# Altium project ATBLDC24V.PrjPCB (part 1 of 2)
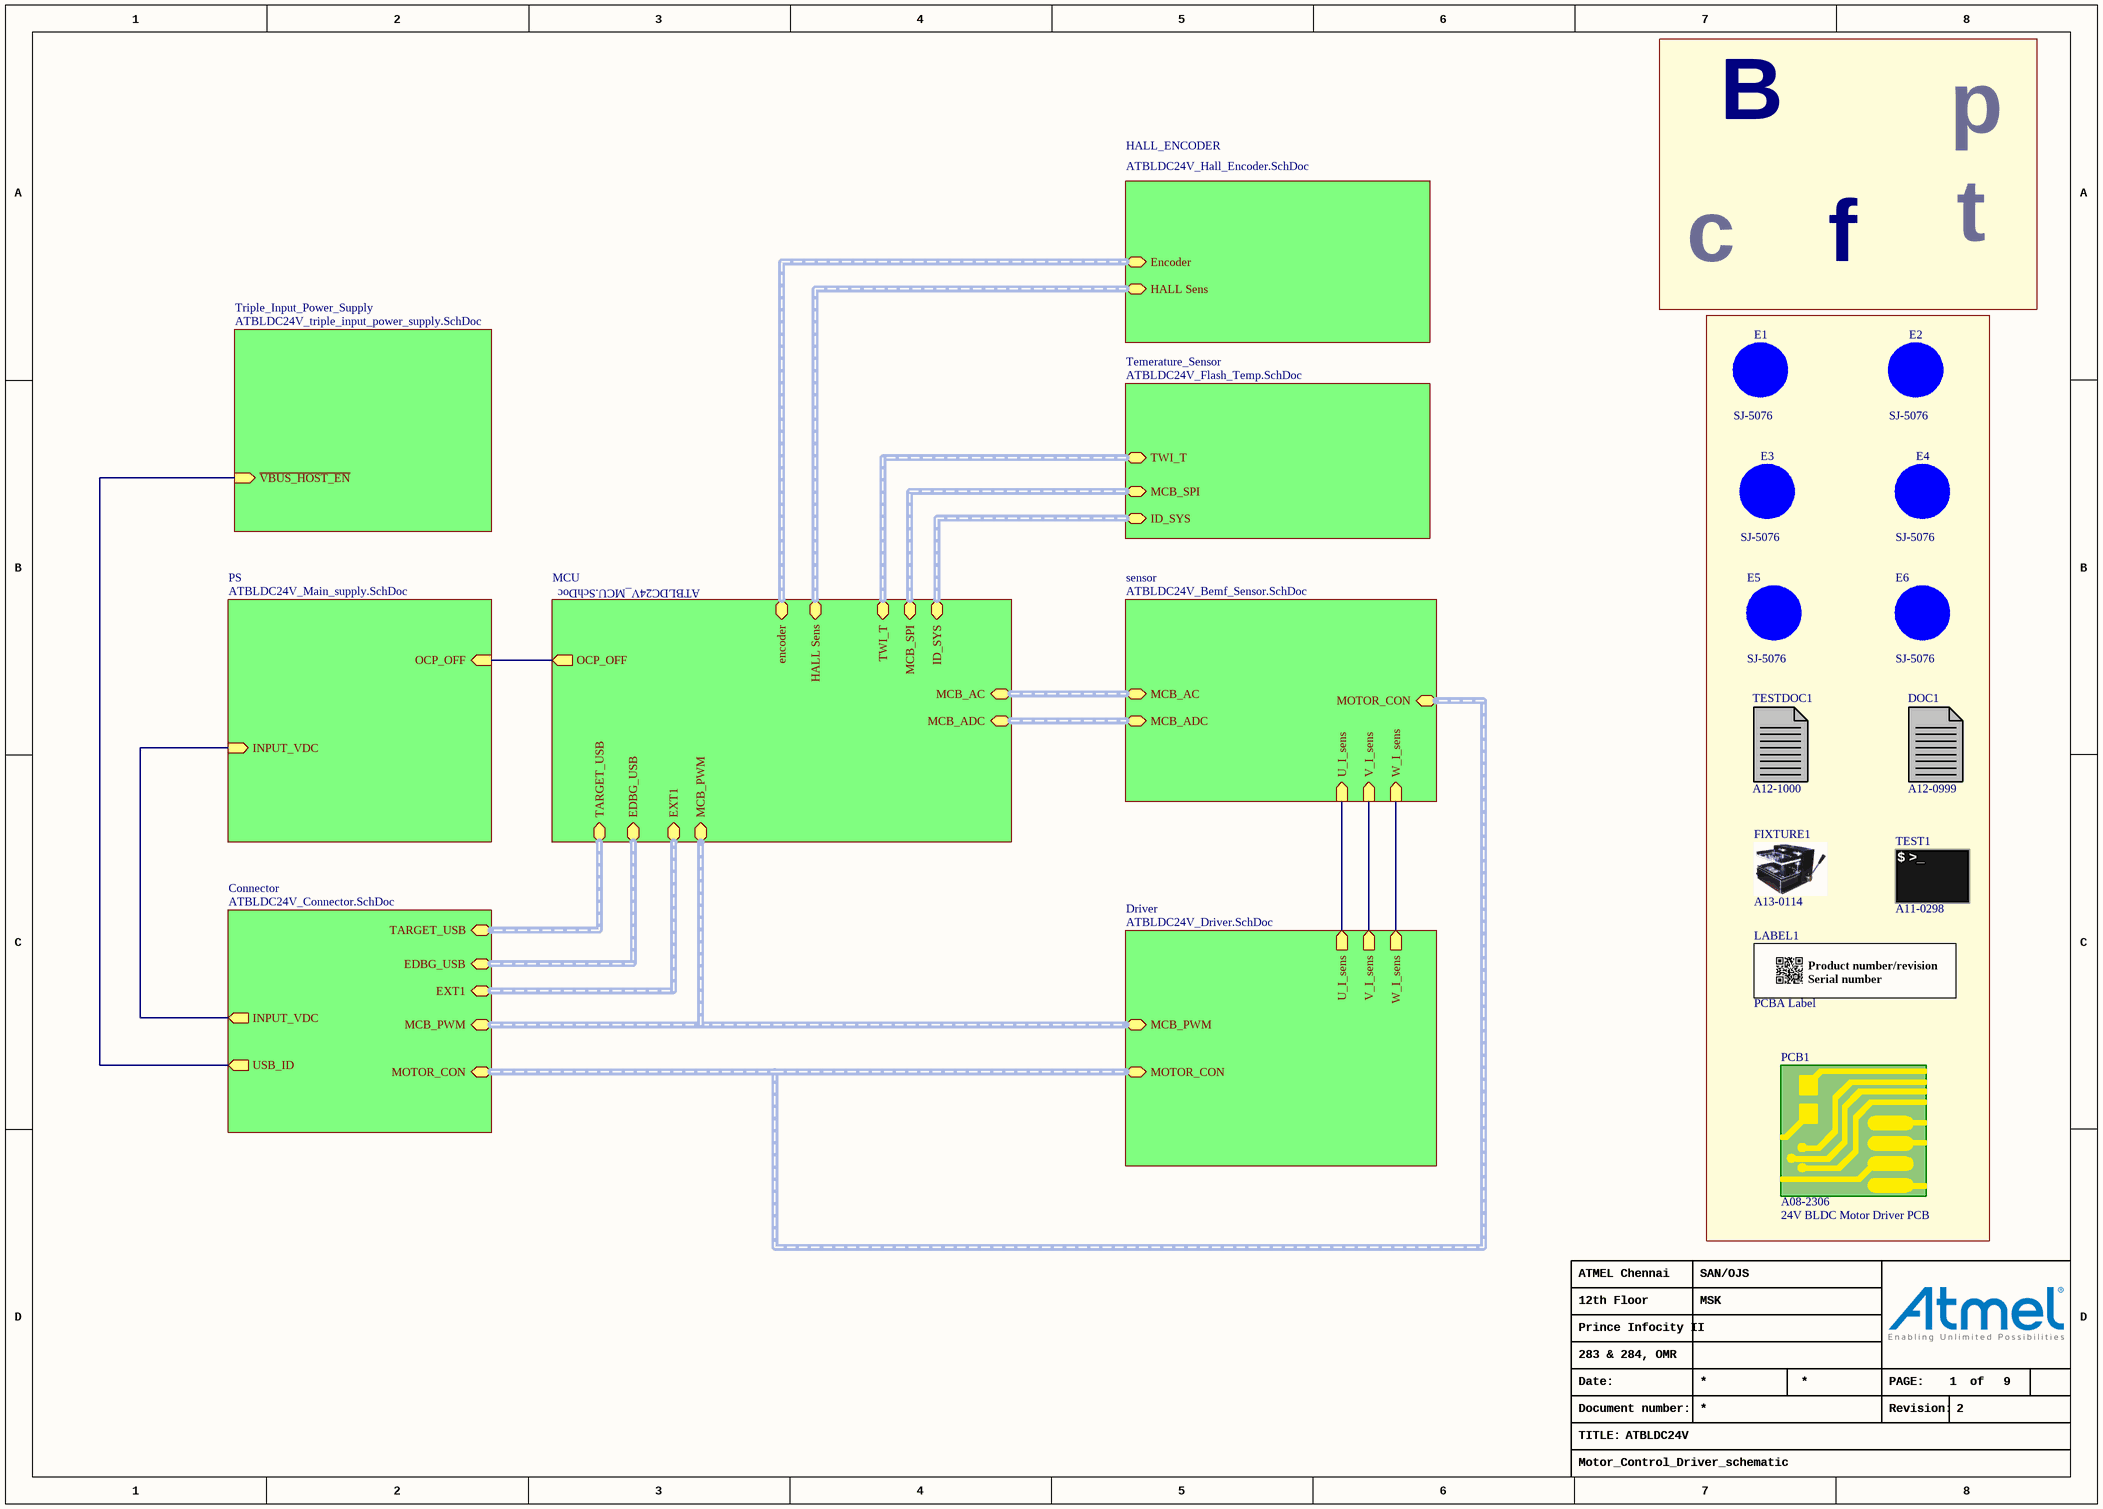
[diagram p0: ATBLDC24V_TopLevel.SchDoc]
9 sheets, 345 parts. Net scope: hierarchical (ports join the sheet entries above them; power ports are global).
Board file: ATBLDC24V.PcbDoc
Sheets:
  ATBLDC24V_TopLevel.SchDoc
    PS = ATBLDC24V_Main_supply.SchDoc
    Driver = ATBLDC24V_Driver.SchDoc
    Connector = ATBLDC24V_Connector.SchDoc
    sensor = ATBLDC24V_Bemf_Sensor.SchDoc
    MCU = ATBLDC24V_MCU.SchDoc
    Temerature_Sensor = ATBLDC24V_Flash_Temp.SchDoc
    Triple_Input_Power_Supply = ATBLDC24V_triple_input_power_supply.SchDoc
    HALL_ENCODER = ATBLDC24V_Hall_Encoder.SchDoc

## Sheet ATBLDC24V_TopLevel.SchDoc: ATBLDC24V
size A3; Organization: ATMEL Chennai; Address1: 12th Floor; Address2: Prince Infocity II; Address3: 283 & 284, OMR; Address4: Chennai; Revision: 2; SheetNumber: 1; SheetTotal: 9; CheckedBy: MSK; DrawnBy: SAN/OJS; Engineer: SAN/OJS; PageSetup: Record=PageOptions¦CenterHorizontal=True¦CenterVertical=True¦PrintScale=0.70¦XCorrection=1.00¦YCorrection=1.00¦PrintKind=0¦BorderSize=5000000¦LeftOffset=0¦BottomOffset=0¦Orientation=2¦PaperLength=1000¦PaperWidth=1000¦Scale=100¦PaperSource=7¦PrintQuality=-4¦MediaType=1¦DitherType=10¦PaperKind=Letter¦PrintScaleMode=1

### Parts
DOC1  AN: A12-0999  (hidden comment: DOCUMENTATION)  (mechanical)
E1  value SJ-5076  [AP8-00192]
E2  value SJ-5076  [AP8-00192]
E3  value SJ-5076  [AP8-00192]
E4  value SJ-5076  [AP8-00192]
E5  value SJ-5076  [AP8-00192]  (hidden comment: RUBBER FEET)
E6  value SJ-5076  [AP8-00192]  (hidden comment: RUBBER FEET)
FIXTURE1  AN: A13-0114  (hidden comment: JIG)  (mechanical)
LABEL1  value PCBA Label  [AP8-00317]  (hidden comment: PCBA_LABEL)
PCB1  value 24V BLDC Motor Driver PCB  AN: A08-2306  (hidden comment: PCB)  (mechanical)
TEST1  AN: A11-0298  (hidden comment: TEST)  (mechanical)
TESTDOC1  AN: A12-1000  (hidden comment: TESTDOC)  (mechanical)

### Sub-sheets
Connector = ATBLDC24V_Connector.SchDoc: EXT1 (harness EXT1), MCB_PWM (harness MCB_PWM), MOTOR_CON (harness MOTOR_CON), INPUT_VDC (out), EDBG_USB (harness EDBG_USB), TARGET_USB (harness TARGET_USB), USB_ID (out)
Driver = ATBLDC24V_Driver.SchDoc: MOTOR_CON (harness MOTOR_CON), MCB_PWM (harness MCB_PWM), W_I_sens (out), V_I_sens (out), U_I_sens (out)
HALL_ENCODER = ATBLDC24V_Hall_Encoder.SchDoc: HALL Sens (harness Hall Sensor), Encoder (harness Encoder)
MCU = ATBLDC24V_MCU.SchDoc: MCB_ADC (harness MCB_ADC), MCB_AC (harness MCB_AC), MCB_PWM (harness MCB_PWM), MCB_SPI (harness MCB_SPI), EXT1 (harness EXT1), ID_SYS (harness ID_SYS), TWI_T (harness TWI_T), EDBG_USB (harness EDBG_USB), TARGET_USB (harness TARGET_USB), HALL Sens (harness Hall Sensor), encoder (harness Encoder), OCP_OFF (out)
PS = ATBLDC24V_Main_supply.SchDoc: INPUT_VDC (in), OCP_OFF (in)
sensor = ATBLDC24V_Bemf_Sensor.SchDoc: MCB_AC (harness MCB_AC), MCB_ADC (harness MCB_ADC), W_I_sens (in), V_I_sens (in), U_I_sens (in), MOTOR_CON (harness MOTOR_CON)
Temerature_Sensor = ATBLDC24V_Flash_Temp.SchDoc: TWI_T (harness TWI_T), ID_SYS (harness ID_SYS), MCB_SPI (harness MCB_SPI)
Triple_Input_Power_Supply = ATBLDC24V_triple_input_power_supply.SchDoc: ~{VBUS_HOST_EN} (in)

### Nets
GPIO8: sheet PS/OCP_OFF, sheet MCU/OCP_OFF
TARGET_USB_ID: sheet Connector/USB_ID, sheet Triple_Input_Power_Supply/~{VBUS_HOST_EN}
USHUNT_ADC: sheet Driver/U_I_sens, sheet sensor/U_I_sens
VSHUNT_ADC: sheet Driver/V_I_sens, sheet sensor/V_I_sens
WSHUNT_ADC: sheet Driver/W_I_sens, sheet sensor/W_I_sens
NetCONN1_1: sheet PS/INPUT_VDC, sheet Connector/INPUT_VDC

Not connected (* = marked no-connect by the designer): E1 1(FIDUCIAL); E2 1(FIDUCIAL); E3 1(FIDUCIAL); E4 1(FIDUCIAL); E5 1(FIDUCIAL); E6 1(FIDUCIAL)

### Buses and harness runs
harness sheet Connector/EDBG_USB = sheet MCU/EDBG_USB
harness sheet Connector/EXT1 = sheet MCU/EXT1
harness sheet Connector/MCB_PWM = sheet Driver/MCB_PWM = sheet MCU/MCB_PWM
harness sheet Connector/MOTOR_CON = sheet Driver/MOTOR_CON = sheet sensor/MOTOR_CON
harness sheet Connector/TARGET_USB = sheet MCU/TARGET_USB
harness sheet HALL_ENCODER/Encoder = sheet MCU/encoder
harness sheet HALL_ENCODER/HALL Sens = sheet MCU/HALL Sens
harness sheet MCU/ID_SYS = sheet Temerature_Sensor/ID_SYS
harness sheet MCU/MCB_AC = sheet sensor/MCB_AC
harness sheet MCU/MCB_ADC = sheet sensor/MCB_ADC
harness sheet MCU/MCB_SPI = sheet Temerature_Sensor/MCB_SPI
harness sheet MCU/TWI_T = sheet Temerature_Sensor/TWI_T

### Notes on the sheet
- B
- p
- c
- f
- t
- Date:
- PAGE:
- of
- TITLE:
- Document number:
- Revision:

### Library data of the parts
DOC1 = A12-0999: 24V BLDC Motor Driver PCBA; PartGroup: Documentation,PCBA Documents,Atmel
E1-E6 = A08-0053: 2.8mm adhesive feet,diam 8.0mm; PartGroup: Mechanical devices,Mounting accessories; Manufacturer: 3M
FIXTURE1 = A13-0114: Test Fixture for BLDC Motor driver; PartGroup: Test Equipment,Test Fixtures
LABEL1 = A09-0611: PCBA identification label PP Top White Gloss; PartGroup: Mechanical devices,Packaging materials,Printed Labels; Manufacturer: ACT Logimark AS; MPN: 505462
PCB1 = A08-2306: 24V BLDC Motor Driver PCB; PartGroup: Mechanical devices,Printed circuit boards; TemperatureRange: -40 deg C to +150 deg C
TEST1 = A11-0298: Fixture test SW for BLDC Motor driver; PartGroup: Software,Test software,Starter Kit
TESTDOC1 = A12-1000: BLDC Motor Driver production Test Instructions; PartGroup: Documentation,Procedures,Test Instructions

## Sheet ATBLDC24V_Main_supply.SchDoc: ATBLDC24V_schematic
size A3; Organization: ATMEL Chennai; Address1: 12th Floor; Address2: Prince Infocity II; Address3: 283 & 284, OMR; Address4: Chennai; Revision: 2; SheetNumber: 2; SheetTotal: 9; CheckedBy: MSK; DrawnBy: SAN/OJS; Engineer: SAN/OJS; PageSetup: Record=PageOptions¦CenterHorizontal=True¦CenterVertical=True¦PrintScale=1.01¦XCorrection=1.00¦YCorrection=1.00¦PrintKind=1¦BorderSize=5000000¦LeftOffset=0¦BottomOffset=0¦Orientation=2¦PaperLength=1000¦PaperWidth=1000¦Scale=100¦PaperSource=7¦PrintQuality=-4¦MediaType=1¦DitherType=10¦PaperKind=A3 (297 x 420 mm)¦PrintScaleMode=1
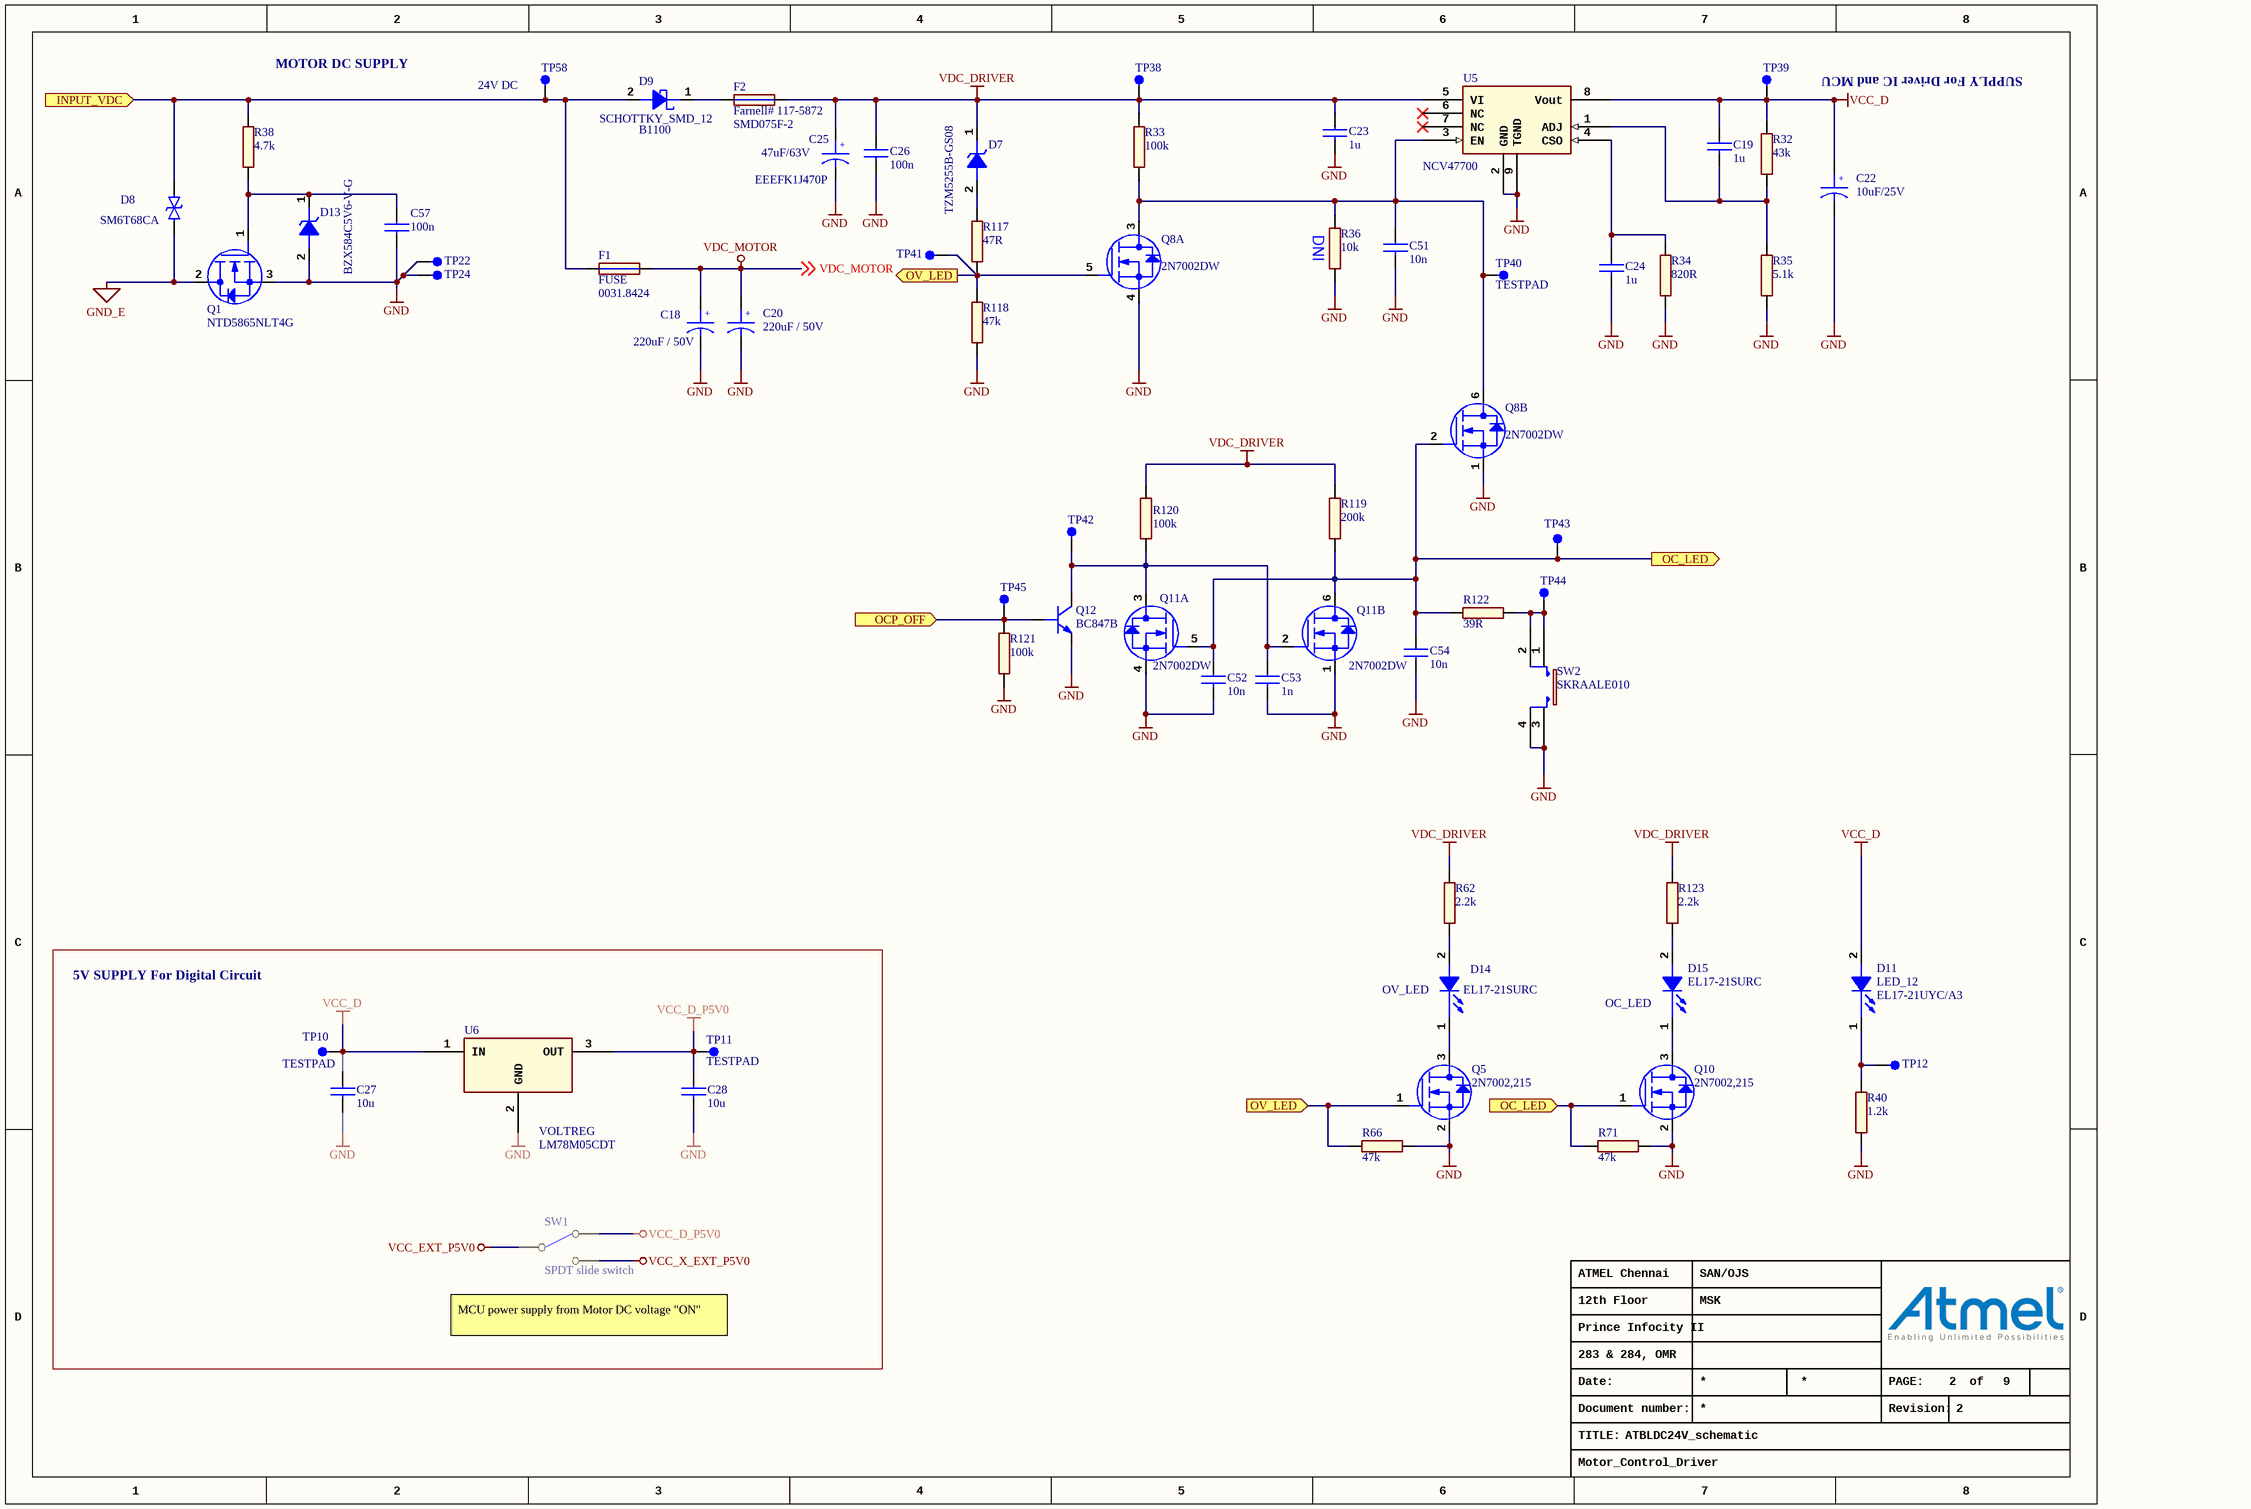
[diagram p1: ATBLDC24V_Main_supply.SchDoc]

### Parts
C18  value 220uF / 50V  [AP1-00025]  (hidden comment: CAP-POL)
C19  value 1u  [AP1-00003]  (hidden comment: CAP-NONPOL)
C20  value 220uF / 50V  [AP1-00025]  (hidden comment: CAP-POL)
C22  value 10uF/25V  [AP1-00013]  (hidden comment: CAP-POL)
C23  value 1u  [AP1-00003]  (hidden comment: CAP-NONPOL)
C24  value 1u  [AP1-00003]  (hidden comment: CAP-NONPOL)
C25  47uF/63V  value EEEFK1J470P  [AP1-00012]
C26  value 100n  [AP1-00003]  (hidden comment: CAP-NONPOL)
C27  value 10u  [AP1-00003]  (hidden comment: CAP-NONPOL)
C28  value 10u  [AP1-00003]  (hidden comment: CAP-NONPOL)
C51  value 10n  [AP1-00002]  (hidden comment: CAP-NONPOL)
C52  value 10n  [AP1-00001]  (hidden comment: CAP-NONPOL)
C53  value 1n  [AP1-00001]  (hidden comment: CAP-NONPOL)
C54  value 10n  [AP1-00001]  (hidden comment: CAP-NONPOL)
C57  value 100n  [AP1-00003]  (hidden comment: CAP-NONPOL)
D7  value TZM5255B-GS08  (hidden comment: ZENER_SMD_12)
D8  value SM6T68CA  [AP4-00002]  (hidden comment: TransGuard)
D9  SCHOTTKY_SMD_12  value B1100  [AP4-00038]
D11  LED_12  value EL17-21UYC/A3  [AP4-00013]
D13  value BZX584C5V6-V-G  [AP4-00036]  (hidden comment: ZENER_SMD_12)
D14  value EL17-21SURC  [AP4-00013]  (hidden comment: LED_12)
D15  value EL17-21SURC  [AP4-00013]  (hidden comment: LED_12)
F1  FUSE  value 0031.8424  [AP8-00249]
F2  Farnell# 117-5872  value SMD075F-2  [AP2-00018]
Q1  value NTD5865NLT4G  (hidden comment: MOSFET_N_DPAK)
Q5  value 2N7002,215  [AP5-00002]  (hidden comment: MOSFET_N_GSD)
Q8  value 2N7002DW  [AP5-00001]  (hidden comment: Same as 2N7002 but with two MOSFETs in one package)  (parts A,B of 2)
Q10  value 2N7002,215  [AP5-00002]  (hidden comment: MOSFET_N_GSD)
Q11  value 2N7002DW  [AP5-00001]  (hidden comment: Same as 2N7002 but with two MOSFETs in one package)  (parts A,B of 2)
Q12  value BC847B  [AP5-00002]  (hidden comment: NPN BEC)
R32  value 43k  [AP2-00001]  (hidden comment: R2)
R33  value 100k  [AP2-00001]  (hidden comment: R2)
R34  value 820R  [AP2-00001]  (hidden comment: R2)
R35  value 5.1k  [AP2-00001]  (hidden comment: R2)
R36  value 10k  [AP2-00000]  (hidden comment: R2)
R38  value 4.7k  [AP2-00001]  (hidden comment: R2)
R40  value 1.2k  [AP2-00001]  (hidden comment: R2)
R62  value 2.2k  [AP2-00001]  (hidden comment: R2)
R66  value 47k  [AP2-00000]  (hidden comment: R2)
R71  value 47k  [AP2-00000]  (hidden comment: R2)
R117  value 47R  [AP2-00001]  (hidden comment: R2)
R118  value 47k  [AP2-00000]  (hidden comment: R2)
R119  value 200k  [AP2-00001]  (hidden comment: R2)
R120  value 100k  [AP2-00001]  (hidden comment: R2)
R121  value 100k  [AP2-00000]  (hidden comment: R2)
R122  value 39R  [AP2-00001]  (hidden comment: R2)
R123  value 2.2k  [AP2-00001]  (hidden comment: R2)
SW1  value SPDT slide switch  [AP8-00431]  (hidden comment: SW_SPDT)
SW2  value SKRAALE010  [AP8-00137]  (hidden comment: PUSHBUTTON1)
TP10  value TESTPAD  [AP8-00010]  (hidden comment: TESTPOINT)  (no BOM)
TP11  value TESTPAD  [AP8-00010]  (hidden comment: TESTPOINT)  (no BOM)
TP12  TESTPOINT  [AP8-00010]  (value not drawn)  (no BOM)
TP22  Mounting hole dia should be 1.6mm. Refer A08-2059  [AP8-00710]  (value not drawn)  (no BOM)
TP24  Mounting hole dia should be 1.6mm. Refer A08-2059  [AP8-00710]  (value not drawn)  (no BOM)
TP38  TESTPOINT  [AP8-00010]  (value not drawn)  (no BOM)
TP39  TESTPOINT  [AP8-00010]  (value not drawn)  (no BOM)
TP40  value TESTPAD  [AP8-00010]  (hidden comment: TESTPOINT)  (no BOM)
TP41  TESTPOINT  [AP8-00010]  (value not drawn)  (no BOM)
TP42  TESTPOINT  [AP8-00010]  (value not drawn)  (no BOM)
TP43  TESTPOINT  [AP8-00010]  (value not drawn)  (no BOM)
TP44  TESTPOINT  [AP8-00010]  (value not drawn)  (no BOM)
TP45  TESTPOINT  [AP8-00010]  (value not drawn)  (no BOM)
TP58  TESTPOINT  [AP8-00010]  (value not drawn)  (no BOM)
U5  value NCV47700  [AP6-00427]  (hidden comment: NCV47710)
U6  VOLTREG  value LM78M05CDT  [AP6-00041]

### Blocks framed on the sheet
5V SUPPLY For Digital Circuit: C27 C28 SW1 TP10 TP11 U6

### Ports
INPUT_VDC (in), OC_LED (in), OC_LED (out), OCP_OFF (in), OV_LED (in), OV_LED (out)

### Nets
GND: C18.2 C20.2 C22.2 C23.2 C24.2 C25.2 C26.2 C27.2 C28.2 C51.2 C52.2 C53.2 C54.2 C57.2 D13.2(ANODE) Q1.3(S) Q5.2(S) Q8.1(S2) Q8.4(S1) Q10.2(S) Q11.1(S2) Q11.4(S1) Q12.2(E) R34.1 R35.2 R36.1 R40.1 R66.1 R71.1 R118.1 R121.1 SW2.3 SW2.4 TP22.1 TP24.1 U5.2(GND) U5.9(TGND) U6.2(GND)
GND_E: D8.2 Q1.2(D)
VCC_D: C19.1 C22.1 C27.1 D11.2(ANODE) R32.2 TP10.1 TP39.1 U5.8(Vout) U6.1(IN)
VCC_D_P5V0: C28.1 SW1.2(NC) TP11.1 U6.3(OUT)
VCC_EXT_P5V0: SW1.1(COMMON)
VCC_X_EXT_P5V0: SW1.3(NO)
VDC_DRIVER: C23.1 C25.1 C26.1 D7.1(CATHODE) F2.1 R33.2 R62.2 R119.2 R120.2 R123.2 TP38.1 U5.5(VI)
VDC_MOTOR: C18.1 C20.1 F1.2 ; off-sheet VDC_MOTOR
GPIO8: Q12.1(B) R121.2 TP45.1 ; port OCP_OFF
NetC19_2: C19.2 R32.1 R35.1 U5.1(ADJ)
NetC24_1: C24.1 R34.2 U5.4(CSO)
NetC51_1: C51.1 Q8.3(D1) Q8.6(D2) R33.1 R36.2 TP40.1 U5.3(EN)
NetC52_1: C52.1 C54.1 Q8.2(G2) Q10.1(G) Q11.5(G1) Q11.6(D2) R71.2 R119.1 R122.2 TP43.1 ; port OC_LED
NetC53_1: C53.1 Q11.2(G2) Q11.3(D1) Q12.3(C) R120.1 TP42.1
NetC57_1: C57.1 D13.1(CATHODE) Q1.1(G) R38.1
NetCONN1_1: D8.1 D9.2(ANODE) F1.1 R38.2 TP58.1 ; port INPUT_VDC
NetD7_2: D7.2(ANODE) R117.2
NetD9_1: D9.1(CATHODE) F2.2
NetD11_1: D11.1(CATHODE) R40.2 TP12.1
NetD14_1: D14.1(CATHODE) Q5.3(D)
NetD14_2: D14.2(ANODE) R62.1
NetD15_1: D15.1(CATHODE) Q10.3(D)
NetD15_2: D15.2(ANODE) R123.1
NetQ5_1: Q5.1(G) Q8.5(G1) R66.2 R117.1 R118.2 TP41.1 ; port OV_LED
NetR122_1: R122.1 SW2.1 SW2.2 TP44.1

Not connected (* = marked no-connect by the designer): U5 6(NC)* 7(NC)*

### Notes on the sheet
- MOTOR DC SUPPLY
- (near TP58) 24V DC
- SUPPLY For Driver IC and MCU
- (near R36) DNI
- (near D14) OV_LED
- (near D15) OC_LED
- (near SW1) MCU power supply from Motor DC voltage "ON"

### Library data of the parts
C18 C20 = A01-0721: Cap Aluminum Lytic 220uF 50V 20% (10 X 10.2mm) SMD 150mA 2000h 105Â°C T/R; PartGroup: Capacitors,Electrolytic,SMD aluminum; Manufacturer: Panasonic; MPN: EEEHA1H221P; TemperatureRange: -40 to +105
C19 C23 C24 = A01-0392: Ceramic capacitor, SMD 0805, X7R, 50V, ±10 %; PartGroup: Capacitors,Ceramic,SMD 0805; Manufacturer: Murata; MPN: GRM21BR71H105KA12L; Tolerance: ±10 %; TemperatureRange: -55 - +125 deg C
C22 = A01-0394: 10uF/25V,SMD tantalum capacitor, precision molded chip, 6032-28 case,; PartGroup: Capacitors,Tantalum; Manufacturer: Kemet; MPN: T491C106M025AC; Tolerance: 20%; TemperatureRange: -55 - +85 deg. C
C25 = A01-0283: SMD aluminium electrolytic capasitor Ø8mm, Max rippel=0.25(@105degC, 100kHz), Tan=0.08; PartGroup: Capacitors,Electrolytic,SMD aluminum; Manufacturer: Panasonic; Tolerance: 63V, 20%; TemperatureRange: -55C to +105C
C26 C57 = A01-0214: Ceramic capacitor, SMD 0805, X7R, 50V, ±10 %; PartGroup: Capacitors,Ceramic,SMD 0805; Manufacturer: Murata; MPN: GRM21BR71E104KA01L; TemperatureRange: -55 - +125 deg C
C27 C28 = A01-0634: Ceramic capacitor, SMD 0805, X5R, 25V, Â±10%; PartGroup: Capacitors,Ceramic,SMD 0805; Manufacturer: Murata; MPN: GRM21BR61E106KA73L; TemperatureRange: -55 Â°C to +85 Â°C
C51 = A01-0113: Ceramic capacitor, SMD 0603, X7R, 50V, Â±10 %; PartGroup: Capacitors,Ceramic,SMD 0603; Manufacturer: AVX; MPN: 06035C103KAT2A; TemperatureRange: -55 - +125 deg C
C52 C54 = A01-0050: Ceramic capacitor, SMD 0402, X7R, 25V, +/-10%; PartGroup: Capacitors,Ceramic,SMD 0402; TemperatureRange: -55 - +125 deg C
C53 = A01-0038: Ceramic capacitor, SMD 0402, X7R, 50V, +/-10%; PartGroup: Capacitors,Ceramic,SMD 0402; TemperatureRange: -55 - +125 deg C
D7 = A04-0180: Zener DIODE 28V, 500MW, SOD80; PartGroup: Diodes,Zener; Manufacturer: vishay; TemperatureRange: -55 to +150 Â°C
D8 = A04-0021: Bidirectional Transient suppression diode, 600W, V(rm)=58.1V, I(rm)=1uA (at Vrm), V(br)=68V, V(cl)=121V (at Ipp = 33A), SMD (SMB package); PartGroup: Diodes,Transient suppression; Manufacturer: ST; TemperatureRange: -40 - +85 deg C
D9 = A04-0138: 1A, 100V, Schottky Barrier Rectifier, SMA; PartGroup: Diodes,Schottky; Manufacturer: Diodes Incorporated; MPN: B1100-13-F; TemperatureRange: -55°C to +125°C
D11 = A10-0019: LED, Yellow, Wave length=591nm, SMD 0805, ±70°; PartGroup: Opto,LEDs,SMD; Manufacturer: Everlight; MPN: 17-21UYC/S530-A3/TR8; TemperatureRange: -40 to +85 deg C
D13 = A04-0133: Zener diode SOD-523, 5.6V, 200mW; PartGroup: Diodes,Zener; Manufacturer: vishay; Tolerance: 5%; TemperatureRange: - 65 to + 150
D14 D15 = A10-0017: LED, Red, Wave length=639nm, SMD 0805, Â±70Â°; PartGroup: Opto,LEDs,SMD; Manufacturer: Everlight; TemperatureRange: -40 to +85 deg C
F1 = A02-0509: SMD holder and fuse 5x20mm, Fast, 6.3A, 250V; PartGroup: Resistors,Fuses; Manufacturer: Schurter; TemperatureRange: -40 to +85 deg C
F2 = A02-0504: PolySwitch Resettable fuse 0.75A, 30V; PartGroup: Resistors,Resettable fuses,SMD; Manufacturer: Raychem; TemperatureRange: -40 to +85 deg C
Q1 = A05-0166: MOSFET N-CH 60V 40A 16MOHM DPAK; PartGroup: Transistors,Power FET,SMD; Manufacturer: ON Semiconductor
Q5 Q10 = A05-0085: N-Channel MOSFET. 60V, 0.300A continuous, 1.2A Peak. RDS(ON) = 3.8Ohm@VGS=4.5V, VGS(th)<2.5V; PartGroup: Transistors,Small signal FET,SMD; Manufacturer: NXP; TemperatureRange: -65 to 150 deg C
Q8 Q11 = A05-0051: Dual N-Channel MOSFET, 60V, 115mA cont,RDS(ON) < 7.5 Ohm @50mA@5V, SOT-363; PartGroup: Transistors,Small signal FET,SMD; Manufacturer: Fairchild; TemperatureRange: -65 to 150 deg C
Q12 = A05-0001: General purpose SMD small signal BJT transistor. Polarity:NPN, Body:SOT23, P(tot)=0.25W, V(ceo)=45V, I(c)=0.1A, h(fe)=200/450, f(t)=100MHz; PartGroup: Transistors,Small signal BJT,SMD; TemperatureRange: -40 - +85 deg. C
R32 = A02-0113: Thick film resistor, SMD 0603, 1/10W, 1%; PartGroup: Resistors,SMD,0603 1%
R33 R120 = A02-0122: Thick film resistor, SMD 0603, 1/10W, 1%; PartGroup: Resistors,SMD,0603 1%; Manufacturer: Panasonic; MPN: ERJ-3EKF1003V
R34 = A02-0072: Thick film resistor, SMD 0603, 1/10W, 1%; PartGroup: Resistors,SMD,0603 1%
R35 = A02-0091: Thick film resistor, SMD 0603, 1/10W, 1%; PartGroup: Resistors,SMD,0603 1%
R36 = A02-0236: Thick film resistor, SMD 0402, 1/16W, 1%; PartGroup: Resistors,SMD,0402 1%; Manufacturer: vishay; MPN: CRCW040210K0FKED; TemperatureRange: -55 - +125 deg C
R38 = A02-0090: Thick film resistor, SMD 0603, 1/10W, 1%; PartGroup: Resistors,SMD,0603 1%
R40 = A02-0076: Thick film resistor, SMD 0603, 1/10W, 1%; PartGroup: Resistors,SMD,0603 1%
R62 R123 = A02-0082: Thick film resistor, SMD 0603, 1/10W, 1%; PartGroup: Resistors,SMD,0603 1%
R66 R71 R118 = A02-0252: Thick film resistor, SMD 0402, 1/16W, 1%; PartGroup: Resistors,SMD,0402 1%; TemperatureRange: -55 - +125 deg C
R117 = A02-0042: Thick film resistor, SMD 0603, 1/10W, 1%; PartGroup: Resistors,SMD,0603 1%; Manufacturer: KOA; MPN: RK73H1JTTD47R0F
R119 = A02-0129: Thick film resistor, SMD 0603, 1/10W, 1%; PartGroup: Resistors,SMD,0603 1%
R121 = A02-0260: Thick film resistor, SMD 0402, 1/16W, 1%; PartGroup: Resistors,SMD,0402 1%; TemperatureRange: -55ï¿½ to +125ï¿½C
R122 = A02-0040: Thick film resistor, SMD 0603, 1/10W, 1%; PartGroup: Resistors,SMD,0603 1%; Manufacturer: KOA; MPN: RK73H1JTTD39R0F
SW1 = A08-0947: Slide Switch, right angle 3 pol, 2 pos, (de20049); PartGroup: Mechanical devices,Switches,THM; Manufacturer: ECE; MPN: ESP2010A; TemperatureRange: -40Â°C - +85Â°C
SW2 = A08-0091: 6.2x6.2 mm SMD tact switch; PartGroup: Mechanical devices,Switches,SMD; Manufacturer: ALPS; TemperatureRange: -30 - +90 deg C
TP10-TP12 TP38-TP45 TP58 = A08-0004: Single SMD testpad; PartGroup: Mechanical devices,Connectors,Test points
TP22 TP24 = A08-1716: THM Test Point, Without Base, 1.0mm Dia. Mounting; PartGroup: Mechanical devices,Other; Manufacturer: Keystone Corp.; Value: 5012
U5 = A06-1249: 5 V to 20 V Adjustable LDO with Adjustable Current Limit and 3.3 V Logic Compatible Enable Input; PartGroup: Integrated Circuits,Regulators,Linear; Manufacturer: ON Semiconductor; MPN: NCV47700PDAJR2G; TemperatureRange: -40Â°C to +150Â°C
U6 = A06-0137: 3-Terminal Positive Voltage Regulator; PartGroup: Integrated Circuits,Regulators,Linear; Manufacturer: National Semiconductor; TemperatureRange: -40 - +125 degC

## Sheet ATBLDC24V_Driver.SchDoc: ATBLDC24V_schematic
size A3; Organization: ATMEL Chennai; Address1: 12th Floor; Address2: Prince Infocity II; Address3: 283 & 284, OMR; Address4: Chennai; Revision: 2; SheetNumber: 5; SheetTotal: 9; CheckedBy: MSK; DrawnBy: SAN/OJS; Engineer: SAN/OJS; PageSetup: Record=PageOptions¦CenterHorizontal=True¦CenterVertical=True¦PrintScale=1.01¦XCorrection=1.00¦YCorrection=1.00¦PrintKind=1¦BorderSize=5000000¦LeftOffset=0¦BottomOffset=0¦Orientation=2¦PaperLength=1000¦PaperWidth=1000¦Scale=100¦PaperSource=7¦PrintQuality=-4¦MediaType=1¦DitherType=10¦PaperKind=A3 (297 x 420 mm)¦PrintScaleMode=1
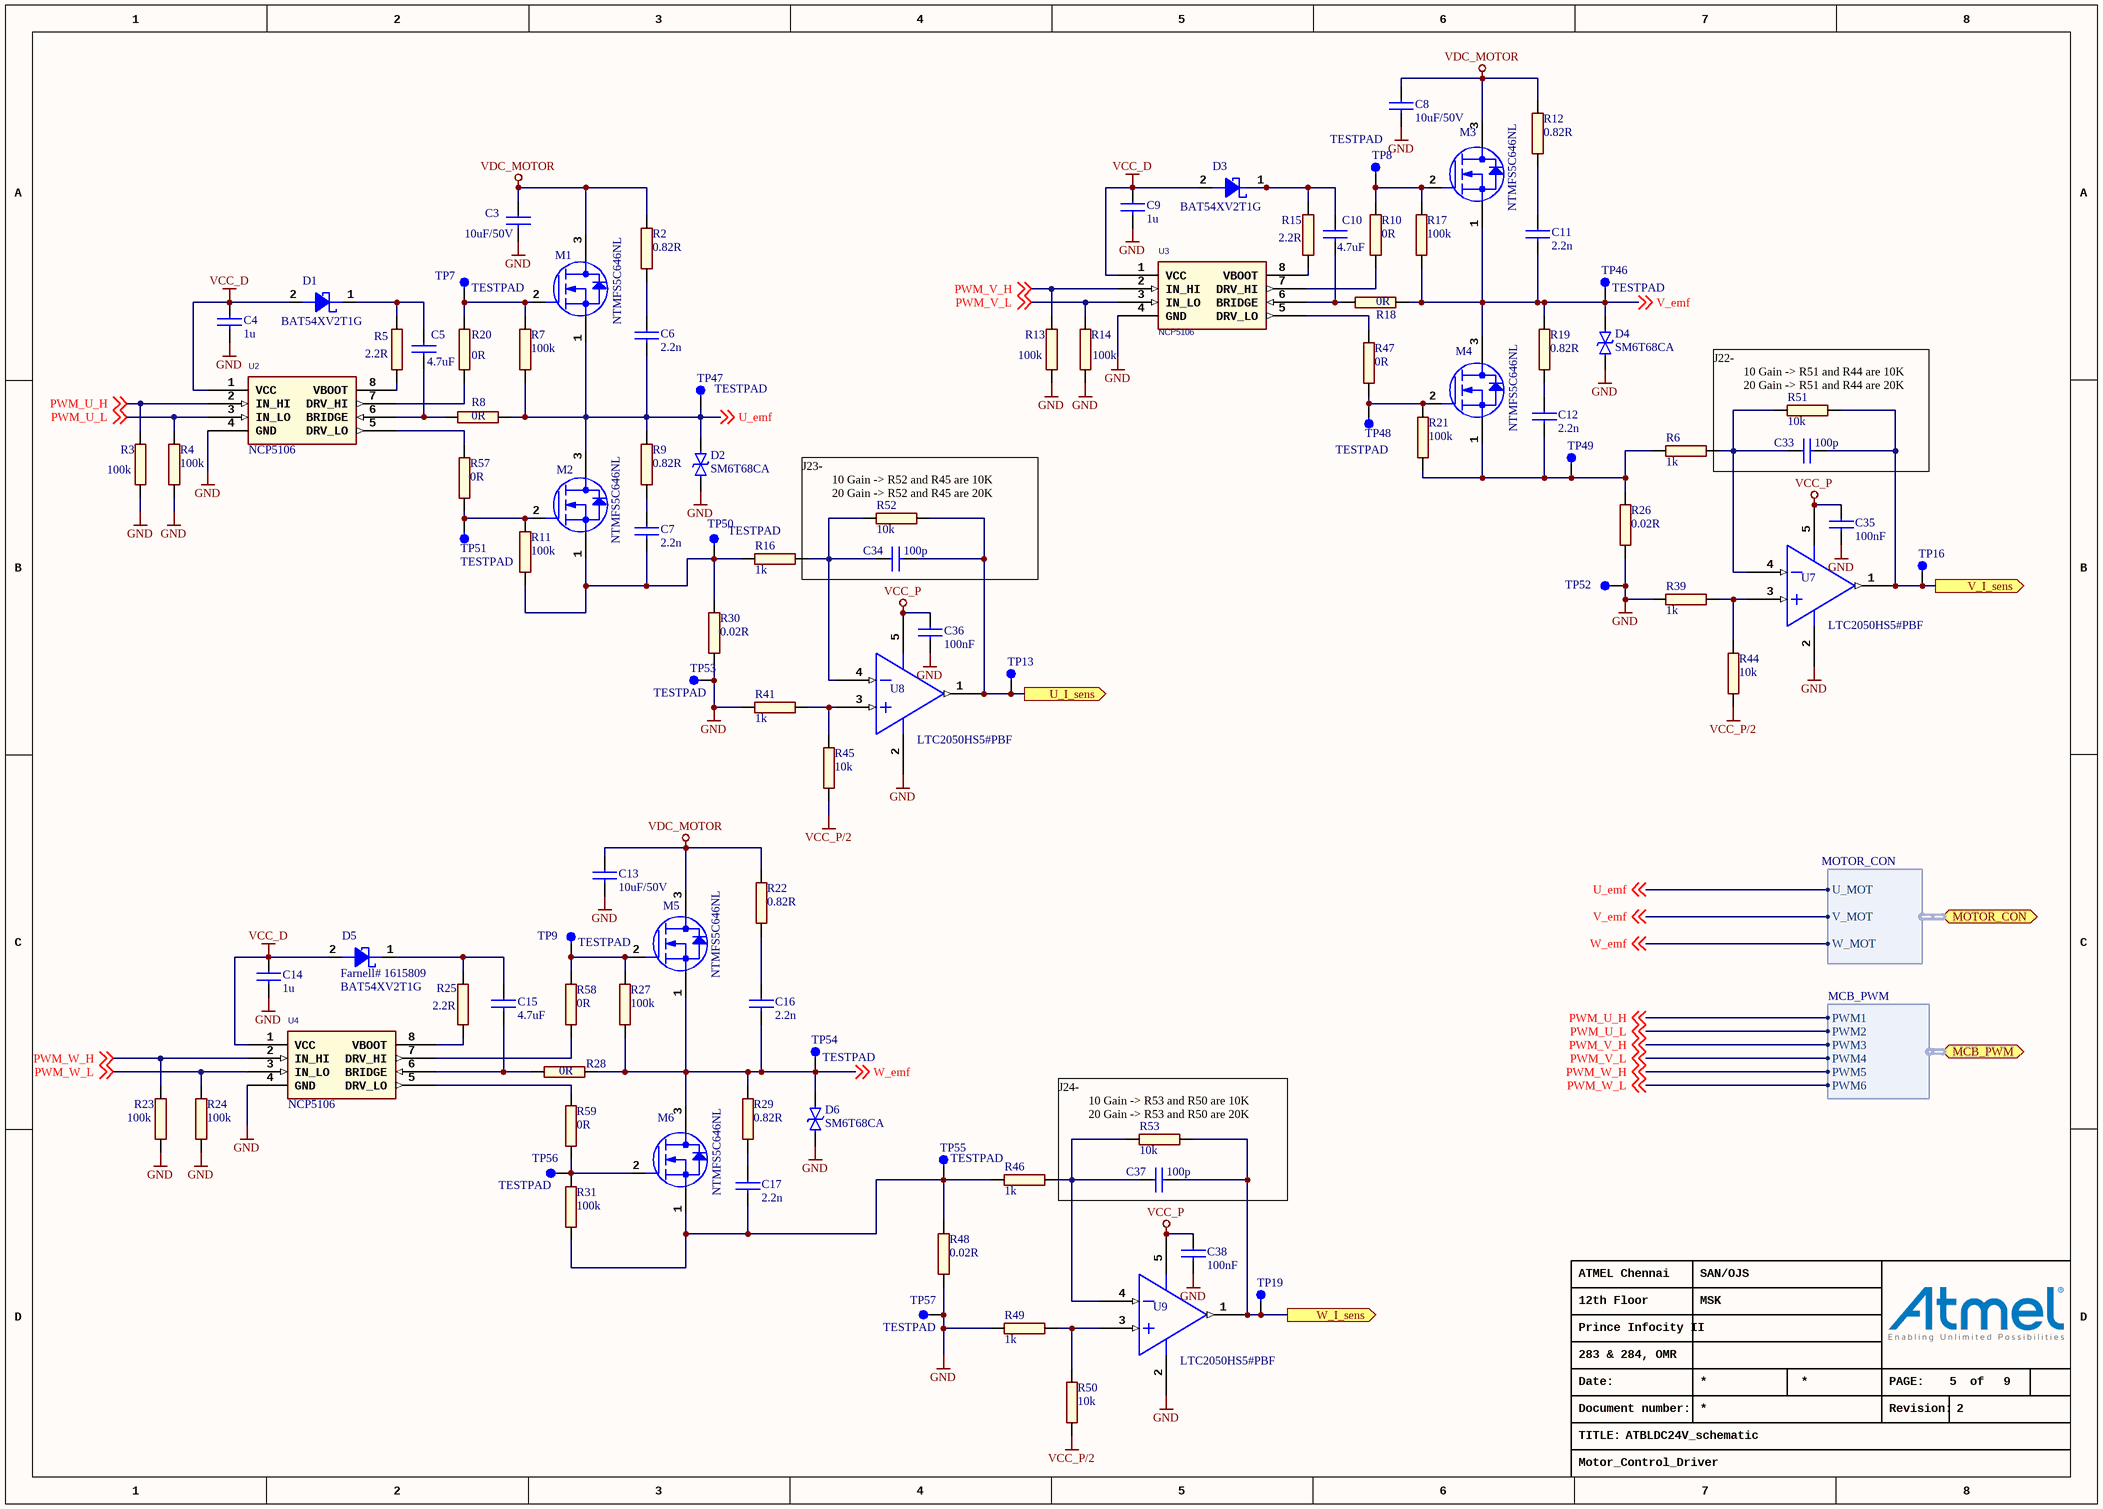
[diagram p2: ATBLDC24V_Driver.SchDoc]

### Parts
C3  value 10uF/50V  [AP1-00015]  (hidden comment: Two similar MPNs from TDK, new and old part number.)
C4  value 1u  [AP1-00003]  (hidden comment: CAP-NONPOL)
C5  value 4.7uF  [AP1-00069]  (hidden comment: CAP-NONPOL)
C6  value 2.2n  [AP1-00003]  (hidden comment: CAP-NONPOL)
C7  value 2.2n  [AP1-00003]  (hidden comment: CAP-NONPOL)
C8  value 10uF/50V  [AP1-00015]  (hidden comment: Two similar MPNs from TDK, new and old part number.)
C9  value 1u  [AP1-00003]  (hidden comment: CAP-NONPOL)
C10  value 4.7uF  [AP1-00069]  (hidden comment: CAP-NONPOL)
C11  value 2.2n  [AP1-00003]  (hidden comment: CAP-NONPOL)
C12  value 2.2n  [AP1-00003]  (hidden comment: CAP-NONPOL)
C13  value 10uF/50V  [AP1-00015]  (hidden comment: Two similar MPNs from TDK, new and old part number.)
C14  value 1u  [AP1-00003]  (hidden comment: CAP-NONPOL)
C15  value 4.7uF  [AP1-00069]  (hidden comment: CAP-NONPOL)
C16  value 2.2n  [AP1-00003]  (hidden comment: CAP-NONPOL)
C17  value 2.2n  [AP1-00003]  (hidden comment: CAP-NONPOL)
C33  value 100p  [AP1-00001]  (hidden comment: CAP-NONPOL)
C34  value 100p  [AP1-00001]  (hidden comment: CAP-NONPOL)
C35  value 100nF  [AP1-00002]  (hidden comment: CAP-NONPOL)
C36  value 100nF  [AP1-00002]  (hidden comment: CAP-NONPOL)
C37  value 100p  [AP1-00001]  (hidden comment: CAP-NONPOL)
C38  value 100nF  [AP1-00002]  (hidden comment: CAP-NONPOL)
D1  value BAT54XV2T1G  [AP4-00036]  (hidden comment: Farnell# 1615809)
D2  value SM6T68CA  [AP4-00002]  (hidden comment: TransGuard)
D3  value BAT54XV2T1G  [AP4-00036]  (hidden comment: Farnell# 1615809)
D4  value SM6T68CA  [AP4-00002]  (hidden comment: TransGuard)
D5  Farnell# 1615809  value BAT54XV2T1G  [AP4-00036]
D6  value SM6T68CA  [AP4-00002]  (hidden comment: TransGuard)
M1  NTMFS5C646NL  [AP5-00048]
M2  NTMFS5C646NL  [AP5-00048]
M3  NTMFS5C646NL  [AP5-00048]
M4  NTMFS5C646NL  [AP5-00048]
M5  NTMFS5C646NL  [AP5-00048]
M6  NTMFS5C646NL  [AP5-00048]
R2  value 0.82R  [AP2-00003]  (hidden comment: R2)
R3  value 100k  [AP2-00000]  (hidden comment: R2)
R4  value 100k  [AP2-00000]  (hidden comment: R2)
R5  value 2.2R  [AP2-00002]  (hidden comment: R2)
R6  value 1k  [AP2-00001]  (hidden comment: Farnell no.: 1717570)
R7  value 100k  [AP2-00001]  (hidden comment: R2)
R8  value 0R  [AP2-00001]  (hidden comment: R2)
R9  value 0.82R  [AP2-00003]  (hidden comment: R2)
R10  value 0R  [AP2-00001]  (hidden comment: R2)
R11  value 100k  [AP2-00001]  (hidden comment: R2)
R12  value 0.82R  [AP2-00003]  (hidden comment: R2)
R13  value 100k  [AP2-00000]  (hidden comment: R2)
R14  value 100k  [AP2-00000]  (hidden comment: R2)
R15  value 2.2R  [AP2-00002]  (hidden comment: R2)
R16  value 1k  [AP2-00001]  (hidden comment: Farnell no.: 1717570)
R17  value 100k  [AP2-00001]  (hidden comment: R2)
R18  value 0R  [AP2-00001]  (hidden comment: R2)
R19  value 0.82R  [AP2-00003]  (hidden comment: R2)
R20  value 0R  [AP2-00001]  (hidden comment: R2)
R21  value 100k  [AP2-00001]  (hidden comment: R2)
R22  value 0.82R  [AP2-00003]  (hidden comment: R2)
R23  value 100k  [AP2-00000]  (hidden comment: R2)
R24  value 100k  [AP2-00000]  (hidden comment: R2)
R25  value 2.2R  [AP2-00002]  (hidden comment: R2)
R26  value 0.02R  [AP2-00080]  (hidden comment: R2)
R27  value 100k  [AP2-00001]  (hidden comment: R2)
R28  value 0R  [AP2-00001]  (hidden comment: R2)
R29  value 0.82R  [AP2-00003]  (hidden comment: R2)
R30  value 0.02R  [AP2-00080]  (hidden comment: R2)
R31  value 100k  [AP2-00001]  (hidden comment: R2)
R39  value 1k  [AP2-00001]  (hidden comment: Farnell no.: 1717570)
R41  value 1k  [AP2-00001]  (hidden comment: Farnell no.: 1717570)
R44  value 10k  [AP2-00001]  (hidden comment: Farnell no.: 1717597)
R45  value 10k  [AP2-00001]  (hidden comment: Farnell no.: 1717597)
R46  value 1k  [AP2-00001]  (hidden comment: Farnell no.: 1717570)
R47  value 0R  [AP2-00001]  (hidden comment: R2)
R48  value 0.02R  [AP2-00080]  (hidden comment: R2)
R49  value 1k  [AP2-00001]  (hidden comment: Farnell no.: 1717570)
R50  value 10k  [AP2-00001]  (hidden comment: Farnell no.: 1717597)
R51  value 10k  [AP2-00001]  (hidden comment: Farnell no.: 1717597)
R52  value 10k  [AP2-00001]  (hidden comment: Farnell no.: 1717597)
R53  value 10k  [AP2-00001]  (hidden comment: Farnell no.: 1717597)
R57  value 0R  [AP2-00001]  (hidden comment: R2)
R58  value 0R  [AP2-00001]  (hidden comment: R2)
R59  value 0R  [AP2-00001]  (hidden comment: R2)
TP7  value TESTPAD  [AP8-00010]  (hidden comment: TESTPOINT)  (no BOM)
TP8  value TESTPAD  [AP8-00010]  (hidden comment: TESTPOINT)  (no BOM)
TP9  value TESTPAD  [AP8-00010]  (hidden comment: TESTPOINT)  (no BOM)
TP13  Through hole with 10mil annular ring  [AP8-00722]  (value not drawn)  (no BOM)
TP16  Through hole with 10mil annular ring  [AP8-00722]  (value not drawn)  (no BOM)
TP19  Through hole with 10mil annular ring  [AP8-00722]  (value not drawn)  (no BOM)
TP46  value TESTPAD  [AP8-00010]  (hidden comment: TESTPOINT)  (no BOM)
TP47  value TESTPAD  [AP8-00010]  (hidden comment: TESTPOINT)  (no BOM)
TP48  value TESTPAD  [AP8-00010]  (hidden comment: TESTPOINT)  (no BOM)
TP49  TESTPOINT  [AP8-00010]  (value not drawn)  (no BOM)
TP50  value TESTPAD  [AP8-00010]  (hidden comment: TESTPOINT)  (no BOM)
TP51  value TESTPAD  [AP8-00010]  (hidden comment: TESTPOINT)  (no BOM)
TP52  TESTPOINT  [AP8-00010]  (value not drawn)  (no BOM)
TP53  value TESTPAD  [AP8-00010]  (hidden comment: TESTPOINT)  (no BOM)
TP54  value TESTPAD  [AP8-00010]  (hidden comment: TESTPOINT)  (no BOM)
TP55  value TESTPAD  [AP8-00010]  (hidden comment: TESTPOINT)  (no BOM)
TP56  value TESTPAD  [AP8-00010]  (hidden comment: TESTPOINT)  (no BOM)
TP57  value TESTPAD  [AP8-00010]  (hidden comment: TESTPOINT)  (no BOM)
U2  NCP5106  [AP6-00000]
U3  NCP5106  [AP6-00000]
U4  NCP5106  [AP6-00000]
U7  LTC2050HS5#PBF  [AP6-00087]
U8  LTC2050HS5#PBF  [AP6-00087]
U9  LTC2050HS5#PBF  [AP6-00087]

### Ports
MCB_PWM (harness MCB_PWM), MOTOR_CON (harness MOTOR_CON), U_I_sens (out), V_I_sens (out), W_I_sens (out)

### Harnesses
MCB_PWM: PWM1, PWM2, PWM3, PWM4, PWM5, PWM6
MOTOR_CON: U_MOT, V_MOT, W_MOT

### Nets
GND: C3.2 C4.2 C8.2 C9.2 C13.2 C14.2 C35.2 C36.2 C38.2 D2.2 D4.2 D6.2 R3.1 R4.2 R13.1 R14.2 R23.1 R24.2 R26.1 R30.1 R39.1 R41.1 R48.1 R49.1 TP52.1 TP53.1 TP57.1 U2.4(GND) U3.4(GND) U4.4(GND) U7.2(GND) U8.2(GND) U9.2(GND)
VCC_D: C4.1 C9.1 C14.1 D1.2(ANODE) D3.2(ANODE) D5.2(ANODE) U2.1(VCC) U3.1(VCC) U4.1(VCC)
VCC_P: C35.1 C36.1 C38.1 U7.5(VCC) U8.5(VCC) U9.5(VCC)
VCC_P/2: R44.1 R45.1 R50.1
VDC_MOTOR: C3.1 C8.1 C13.1 M1.3(D) M3.3(D) M5.3(D) R2.2 R12.2 R22.2
PWM_U_H: R3.2 U2.2(IN_HI) ; off-sheet PWM_U_H, port MCB_PWM.PWM1  [project net PWM_UH]
PWM_U_L: R4.1 U2.3(IN_LO) ; off-sheet PWM_U_L, port MCB_PWM.PWM2  [project net PWM_UL]
PWM_V_H: R13.2 U3.2(IN_HI) ; off-sheet PWM_V_H, port MCB_PWM.PWM3  [project net PWM_VH]
PWM_V_L: R14.1 U3.3(IN_LO) ; off-sheet PWM_V_L, port MCB_PWM.PWM4  [project net PWM_VL]
PWM_W_H: R23.2 U4.2(IN_HI) ; off-sheet PWM_W_H, port MCB_PWM.PWM5  [project net PWM_WH]
PWM_W_L: R24.1 U4.3(IN_LO) ; off-sheet PWM_W_L, port MCB_PWM.PWM6  [project net PWM_WL]
U_emf: C6.2 D2.1 M1.1(S) M2.3(D) R7.1 R8.2 R9.2 TP47.1 ; off-sheet U_emf, port MOTOR_CON.U_MOT
USHUNT_ADC: C34.2 R52.2 TP13.1 U8.1(OUT) ; port U_I_sens
V_emf: C11.2 D4.1 M3.1(S) M4.3(D) R17.1 R18.2 R19.2 TP46.1 ; off-sheet V_emf, port MOTOR_CON.V_MOT
VSHUNT_ADC: C33.2 R51.2 TP16.1 U7.1(OUT) ; port V_I_sens
W_emf: C16.2 D6.1 M5.1(S) M6.3(D) R27.1 R28.2 R29.2 TP54.1 ; off-sheet W_emf, port MOTOR_CON.W_MOT
WSHUNT_ADC: C37.2 R53.2 TP19.1 U9.1(OUT) ; port W_I_sens
NetC5_1: C5.1 D1.1(CATHODE) R5.2
NetC5_2: C5.2 R8.1 U2.6(BRIDGE)
NetC6_1: C6.1 R2.1
NetC7_1: C7.1 R9.1
NetC7_2: C7.2 M2.1(S) R11.1 R16.1 R30.2 TP50.1
NetC10_1: C10.1 D3.1(CATHODE) R15.2
NetC10_2: C10.2 R18.1 U3.6(BRIDGE)
NetC11_1: C11.1 R12.1
NetC12_1: C12.1 R19.1
NetC12_2: C12.2 M4.1(S) R6.1 R21.1 R26.2 TP49.1
NetC15_1: C15.1 D5.1(CATHODE) R25.2
NetC15_2: C15.2 R28.1 U4.6(BRIDGE)
NetC16_1: C16.1 R22.1
NetC17_1: C17.1 R29.1
NetC17_2: C17.2 M6.1(S) R31.1 R46.1 R48.2 TP55.1
NetC33_1: C33.1 R6.2 R51.1 U7.4(IN-)
NetC34_1: C34.1 R16.2 R52.1 U8.4(IN-)
NetC37_1: C37.1 R46.2 R53.1 U9.4(IN-)
NetM1_2: M1.2(G) R7.2 R20.2 TP7.1
NetM2_2: M2.2(G) R11.2 R57.1 TP51.1
NetM3_2: M3.2(G) R10.2 R17.2 TP8.1
NetM4_2: M4.2(G) R21.2 R47.1 TP48.1
NetM5_2: M5.2(G) R27.2 R58.2 TP9.1
NetM6_2: M6.2(G) R31.2 R59.1 TP56.1
NetR5_1: R5.1 U2.8(VBOOT)
NetR10_1: R10.1 U3.7(DRV_HI)
NetR15_1: R15.1 U3.8(VBOOT)
NetR20_1: R20.1 U2.7(DRV_HI)
NetR25_1: R25.1 U4.8(VBOOT)
NetR39_2: R39.2 R44.2 U7.3(IN+)
NetR41_2: R41.2 R45.2 U8.3(IN+)
NetR47_2: R47.2 U3.5(DRV_LO)
NetR49_2: R49.2 R50.2 U9.3(IN+)
NetR57_2: R57.2 U2.5(DRV_LO)
NetR58_1: R58.1 U4.7(DRV_HI)
NetR59_2: R59.2 U4.5(DRV_LO)

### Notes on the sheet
- J22-
  10 Gain -> R51 and R44 are 10K
  20 Gain -> R51 and R44 are 20K
- J23-
  10 Gain -> R52 and R45 are 10K
  20 Gain -> R52 and R45 are 20K
- J24-
  10 Gain -> R53 and R50 are 10K
  20 Gain -> R53 and R50 are 20K

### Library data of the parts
C3 C8 C13 = A01-0586: Ceramic capacitor, SMD 1210, X7S , 50V, Â±10%; PartGroup: Capacitors,Ceramic,SMD 1210; MPN: CGA6P3X7S1H106K250AB; TemperatureRange: -55 - +125 deg C
C4 C9 C14 = A01-0392: as C19 on sheet ATBLDC24V_Main_supply
C5 C10 C15 = A01-0498: CAP CER 4.7UF 50V 10% X5R 0805; PartGroup: Capacitors,Ceramic,SMD 0805; Manufacturer: tdk; MPN: C2012X5R1H475K; Tolerance: +/-10%; TemperatureRange: -55 to 85C
C6 C7 C11 C12 C16 C17 = A01-0194: Ceramic capacitor, SMD 0805, X7R, 50V, ±10 %; PartGroup: Capacitors,Ceramic,SMD 0805; TemperatureRange: -55 - +125 deg C
C33 C34 C37 = A01-0027: Ceramic capacitor, SMD 0402, NP0, 50V, +/-10% (de16673); PartGroup: Capacitors,Ceramic,SMD 0402; Manufacturer: Murata; MPN: GRM1555C1H101JZ01D; TemperatureRange: -55 - +125 deg C
C35 C36 C38 = A01-0367: Ceramic capacitor, SMD 0603, X7R, 50V, Â±10 %; PartGroup: Capacitors,Ceramic,SMD 0603; Manufacturer: AVX; MPN: 06035C104KAT2A
D1 D3 D5 = A04-0049: Schottky diode, If:200mA, Vf:0.35V, Vrrm:30V, SOD-523; PartGroup: Diodes,Schottky; Manufacturer: ON Semiconductor; TemperatureRange: -55°C to +125°C
D2 D4 D6 = A04-0021: as D8 on sheet ATBLDC24V_Main_supply
M1-M6 = A05-0152: 60V, 4.7mA , 89A, Single Nâˆ’Channel MOSFET, SOâˆ’8FL; PartGroup: Transistors,Power FET,SMD; Manufacturer: ON Semiconductor; MPN: NTMFS4983NFT1G; TemperatureRange: 55 to +150
R2 R9 R12 R19 R22 R29 = A02-0994: RESISTOR, 1206, 0R82, 1%, 0.5W; PartGroup: Resistors,SMD,1206 1%; Manufacturer: Bourns; MPN: CRM1206-FX-R820ELF
R3 R4 R13 R14 R23 R24 = A02-0260: as R121 on sheet ATBLDC24V_Main_supply
R5 R15 R25 = A02-0294: Thick film resistor, SMD 0805, 0.125W, 1%; PartGroup: Resistors,SMD,0805 1%; Manufacturer: Agilent Technologies
R6 R16 R39 R41 R46 R49 = A02-0960: 1.0K 0.1%, resistor in 0603 at 100mW, TEMPCO 10ppm/C, Max V=75V; PartGroup: Resistors,Metal film,SMD Precision resistors; Manufacturer: Panasonic; MPN: ERA3ARB102P; TemperatureRange: -55 to 155 deg C
R7 R11 R17 R21 R27 R31 = A02-0122: as R33 on sheet ATBLDC24V_Main_supply
R8 R10 R18 R20 R28 R47 R57-R59 = A02-0001: Thick film resistor, SMD 0603, 1/10W, 1%; PartGroup: Resistors,SMD,0603 1%; Manufacturer: Panasonic; MPN: ERJ-3GEY0R00V
R26 R30 R48 = A02-0996: RES, METAL STRIP, R02, 1%, 5W, SMD 4527; PartGroup: Resistors,Sense resistors,SMD Current Sense; Manufacturer: vishay; MPN: WSR5R0200FEA
R44 R45 R50-R53 = A02-0959: 10K 0.1%, resistor in 0603 at 100mW, TEMPCO 10ppm/C, Max V=75V; PartGroup: Resistors,Metal film,SMD Precision resistors; Manufacturer: Panasonic; MPN: ERA3ARB103P; TemperatureRange: -55 to +155 deg C
TP7-TP9 TP46-TP57 = A08-0004: as TP10 on sheet ATBLDC24V_Main_supply
TP13 TP16 TP19 = A08-1748: Single thru-hole testpin; PartGroup: Mechanical devices,Connectors,Test points; Value: 40mil Through Hole Testpoint
U2-U4 = A06-1250: High Voltage, High and Low Side MOSFET Driver; PartGroup: Integrated Circuits,Special function,Drivers; Manufacturer: ON Semiconductor; MPN: NCP5106ADR2G; TemperatureRange: âˆ’55 to +150
U7-U9 = A06-1252: Op Amps High Temp RR Op Amp 2.5V to 5.5V; PartGroup: Integrated Circuits,General linear,OP-AMP; Manufacturer: Linear Technology; TemperatureRange: 0Â°C to +85Â°C

## Sheet ATBLDC24V_Connector.SchDoc: ATBLDC24V_schematic
size A3; Organization: ATMEL Chennai; Address1: 12th Floor; Address2: Prince Infocity II; Address3: 283 & 284, OMR; Address4: Chennai; Revision: 2; SheetNumber: 9; SheetTotal: 9; CheckedBy: MSK; DrawnBy: SAN/OJS; Engineer: SAN/OJS; PageSetup: Record=PageOptions¦CenterHorizontal=True¦CenterVertical=True¦PrintScale=1.01¦XCorrection=1.00¦YCorrection=1.00¦PrintKind=1¦BorderSize=5000000¦LeftOffset=0¦BottomOffset=0¦Orientation=2¦PaperLength=1000¦PaperWidth=1000¦Scale=100¦PaperSource=7¦PrintQuality=-4¦MediaType=1¦DitherType=10¦PaperKind=A3 (297 x 420 mm)¦PrintScaleMode=1
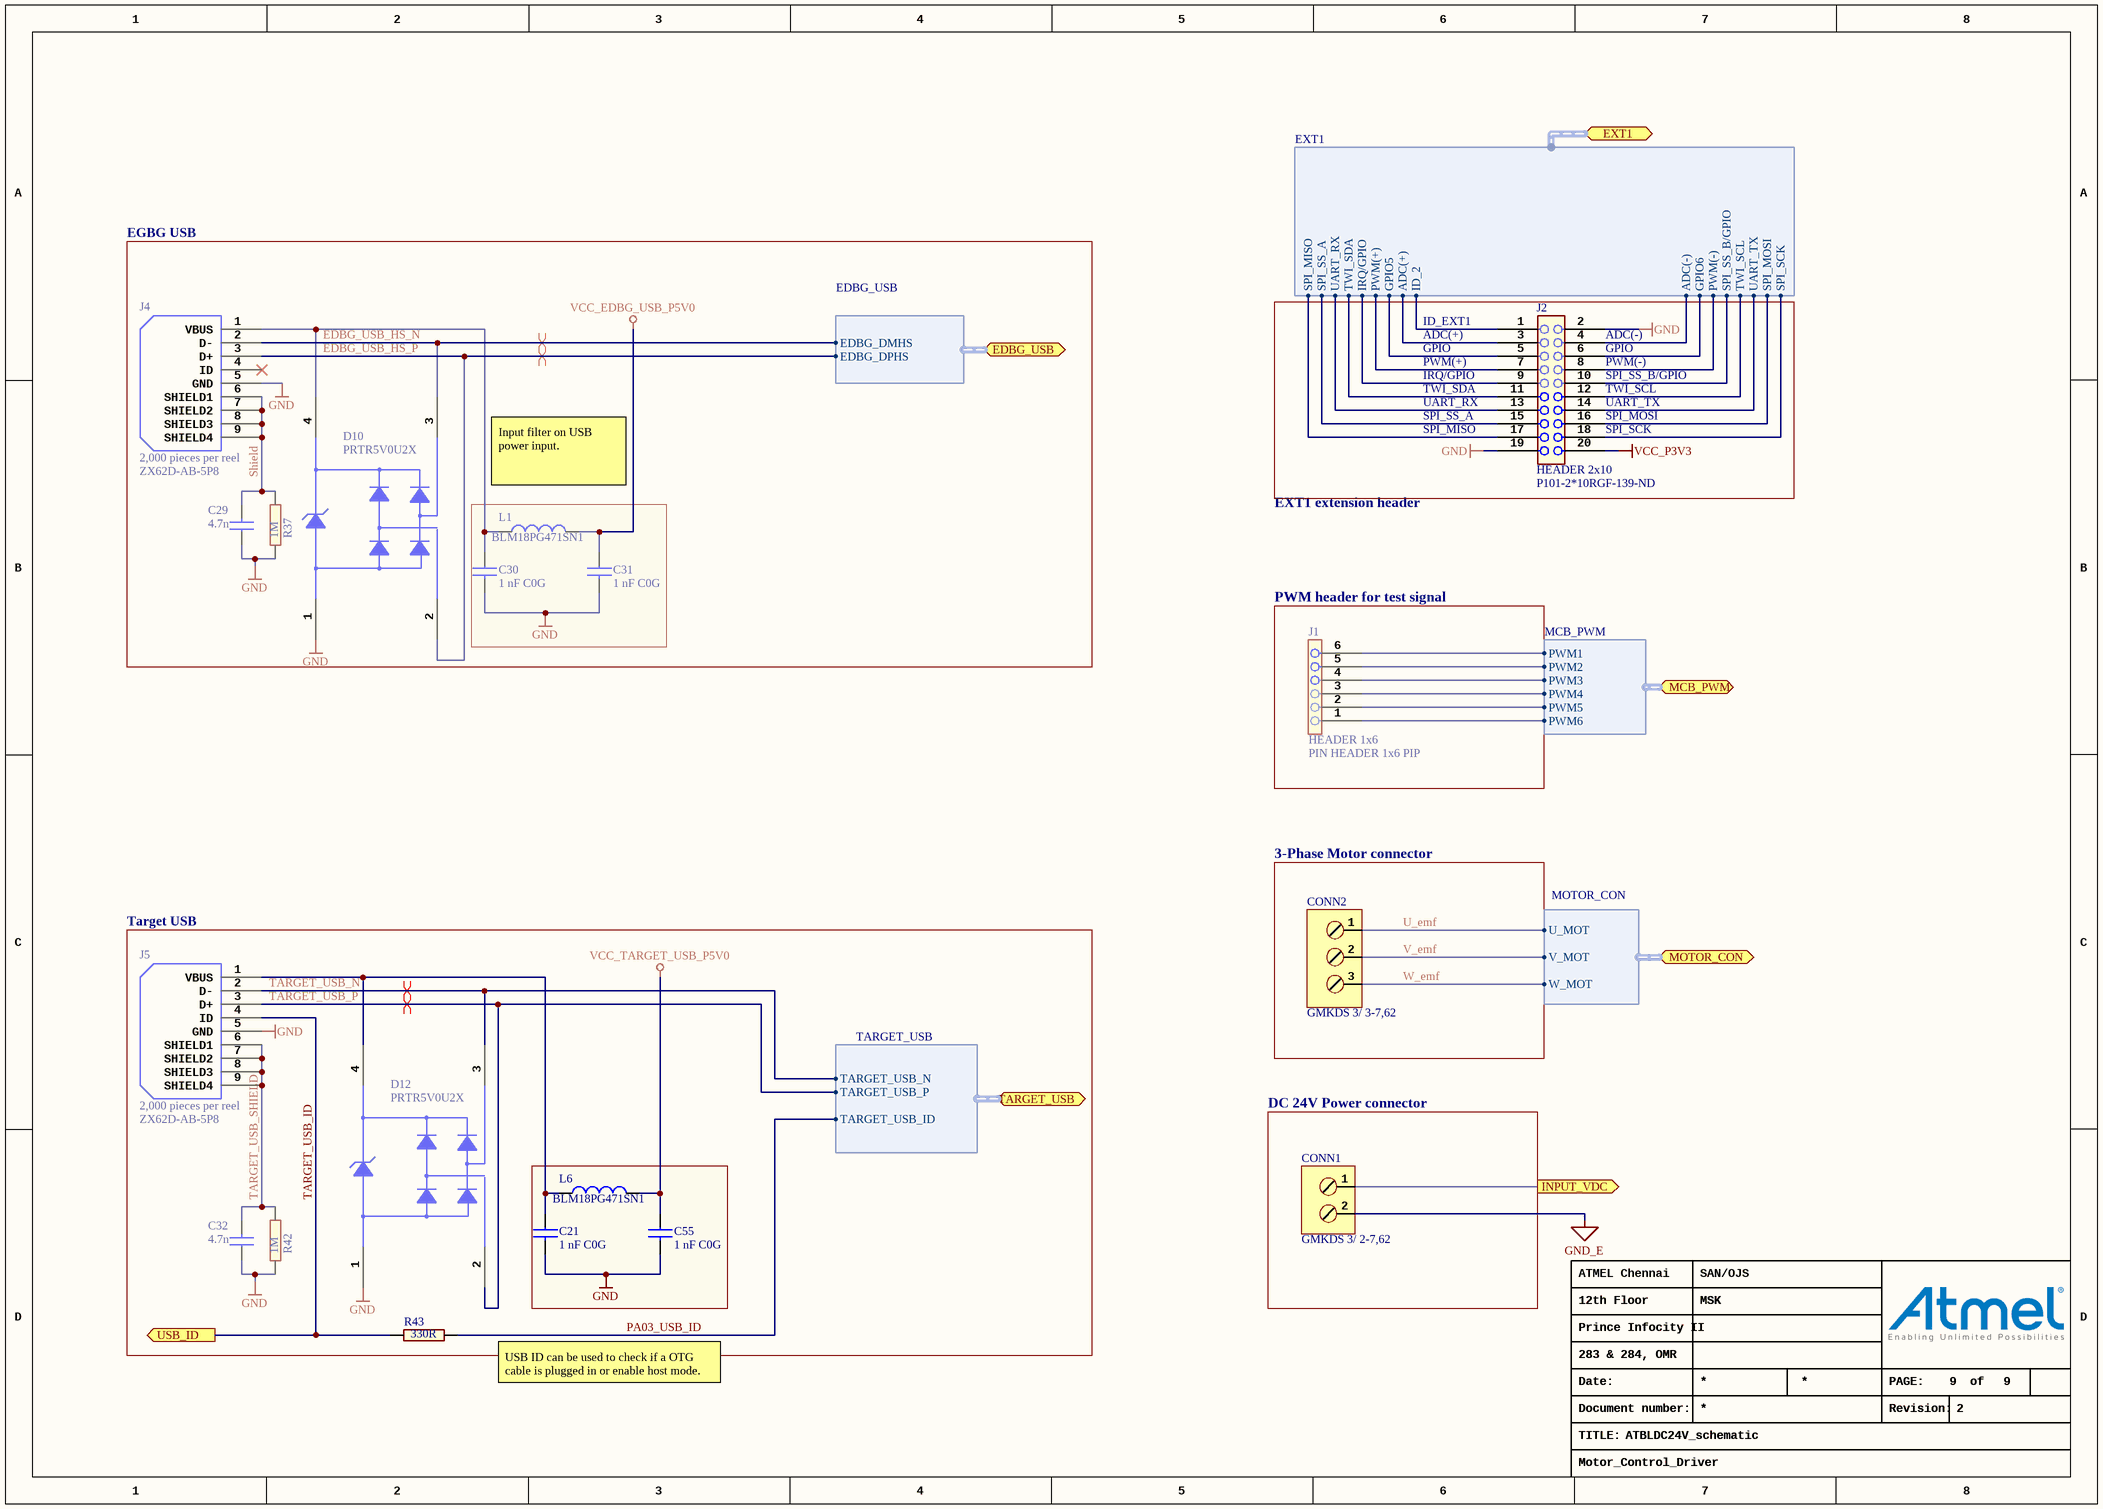
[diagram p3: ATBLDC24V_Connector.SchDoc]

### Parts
C21  1 nF C0G  [AP1-00053]
C29  value 4.7n  [AP1-00053]  (hidden comment: CAP-NONPOL)
C30  1 nF C0G  [AP1-00053]
C31  1 nF C0G  [AP1-00053]
C32  value 4.7n  [AP1-00053]  (hidden comment: CAP-NONPOL)
C55  1 nF C0G  [AP1-00053]
CONN1  value GMKDS 3/ 2-7,62  [AP8-00979]  (hidden comment: Screw Terminal Block 2-way)
CONN2  value GMKDS 3/ 3-7,62  [AP8-00980]  (hidden comment: Farnell no.: 2008004)
D10  PRTR5V0U2X  [AP4-00001]
D12  PRTR5V0U2X  [AP4-00001]
J1  HEADER 1x6  value PIN HEADER 1x6 PIP  [AP8-00177]
J2  HEADER 2x10  value P101-2*10RGF-139-ND  [AP8-00622]
J4  2,000 pieces per reel  value ZX62D-AB-5P8  [AP8-00852]
J5  2,000 pieces per reel  value ZX62D-AB-5P8  [AP8-00852]
L1  BLM18PG471SN1  [AP3-00005]
L6  BLM18PG471SN1  [AP3-00005]
R37  value 1M  [AP2-00011]  (hidden comment: R2)
R42  value 1M  [AP2-00011]  (hidden comment: R2)
R43  value 330R  [AP2-00000]  (hidden comment: R2)

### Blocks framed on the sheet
EGBG USB: C29-C31 D10 J4 L1 R37
PWM header for test signal: J1
3-Phase Motor connector: CONN2
Target USB: C21 C32 C55 D12 J5 L6 R42 R43
DC 24V Power connector: CONN1

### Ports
EDBG_USB (harness EDBG_USB), EXT1 (harness EXT1), INPUT_VDC (out), MCB_PWM (harness MCB_PWM), MOTOR_CON (harness MOTOR_CON), TARGET_USB (harness TARGET_USB), USB_ID (out)

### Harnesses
MOTOR_CON: U_MOT, V_MOT, W_MOT
EXT1: ADC(+), ADC(-), GPIO5, GPIO6, PWM(+), PWM(-), IRQ/GPIO, SPI_SS_B/GPIO, TWI_SDA, TWI_SCL, UART_RX, UART_TX, SPI_SS_A, SPI_MOSI, SPI_MISO, SPI_SCK, ID_2
MCB_PWM: PWM1, PWM2, PWM3, PWM4, PWM5, PWM6
EDBG_USB: EDBG_DMHS, EDBG_DPHS
TARGET_USB: TARGET_USB_N, TARGET_USB_P, TARGET_USB_ID

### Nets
GND: C21.2 C29.1 C30.2 C31.2 C32.1 C55.2 D10.1(GND) D12.1(GND) J2.2 J2.19 J4.5(GND) J5.5(GND) R37.1 R42.1
GND_E: CONN1.2(NC)
VCC_EDBG_USB_P5V0: C31.1 L1.2
VCC_P3V3: J2.20
VCC_TARGET_USB_P5V0: C55.1 L6.2
EDBG_ID2: J2.1 ; port EXT1.ID_2
EDBG_USB_HS_N: D10.3(I/O_2) J4.2(D-) ; port EDBG_USB.EDBG_DMHS
EDBG_USB_HS_P: D10.2(I/O_1) J4.3(D+) ; port EDBG_USB.EDBG_DPHS
PA03_USB_ID: R43.2 ; port TARGET_USB.TARGET_USB_ID
PWM_UH: J1.6 ; port MCB_PWM.PWM1
PWM_UL: J1.5 ; port MCB_PWM.PWM2
PWM_VH: J1.4 ; port MCB_PWM.PWM3
PWM_VL: J1.3 ; port MCB_PWM.PWM4
PWM_WH: J1.2 ; port MCB_PWM.PWM5
PWM_WL: J1.1 ; port MCB_PWM.PWM6
Shield: C29.2 J4.6(SHIELD1) J4.7(SHIELD2) J4.8(SHIELD3) J4.9(SHIELD4) R37.2
SPI_MISO: J2.17 ; port EXT1.SPI_MISO
SPI_MOSI: J2.16 ; port EXT1.SPI_MOSI
SPI_SCK: J2.18 ; port EXT1.SPI_SCK
TARGET_USB_ID: J5.4(ID) R43.1 ; port USB_ID
TARGET_USB_N: D12.3(I/O_2) J5.2(D-) ; port TARGET_USB.TARGET_USB_N  [project net TARGET_USB_HS_N]
TARGET_USB_P: D12.2(I/O_1) J5.3(D+) ; port TARGET_USB.TARGET_USB_P  [project net TARGET_USB_HS_P]
TARGET_USB_SHIELD: C32.2 J5.6(SHIELD1) J5.7(SHIELD2) J5.8(SHIELD3) J5.9(SHIELD4) R42.2
TWI_SCL: J2.12 ; port EXT1.TWI_SCL
TWI_SDA: J2.11 ; port EXT1.TWI_SDA
U_emf: CONN2.1(NC) ; port MOTOR_CON.U_MOT
V_emf: CONN2.2(NC) ; port MOTOR_CON.V_MOT
W_emf: CONN2.3(NC) ; port MOTOR_CON.W_MOT
NetC21_1: C21.1 D12.4(VCC) J5.1(VBUS) L6.1
NetC30_1: C30.1 D10.4(VCC) J4.1(VBUS) L1.1
NetCONN1_1: CONN1.1(NC) ; port INPUT_VDC
NetJ2_3: J2.3 ; port EXT1.ADC(+)
NetJ2_4: J2.4 ; port EXT1.ADC(-)
NetJ2_5: J2.5 ; port EXT1.GPIO5
NetJ2_6: J2.6 ; port EXT1.GPIO6
NetJ2_7: J2.7 ; port EXT1.PWM(+)
NetJ2_8: J2.8 ; port EXT1.PWM(-)
NetJ2_9: J2.9 ; port EXT1.IRQ/GPIO
NetJ2_10: J2.10 ; port EXT1.SPI_SS_B/GPIO
NetJ2_13: J2.13 ; port EXT1.UART_RX
NetJ2_14: J2.14 ; port EXT1.UART_TX
NetJ2_15: J2.15 ; port EXT1.SPI_SS_A

Not connected (* = marked no-connect by the designer): J4 4(ID)*

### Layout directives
differential pair; rule Assembly Testpoint Usage [Testpoint - Not Allowed    Multiple - Not Allowed]: EDBG_USB_HS_N, EDBG_USB_HS_P, TARGET_USB_HS_N, TARGET_USB_HS_P

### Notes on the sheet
- ID_EXT1
- ADC(+)
- GPIO
- PWM(+)
- IRQ/GPIO
- (near J2) ADC(-)
- (near J2) GPIO
- (near J2) PWM(-)
- (near J2) SPI_SS_B/GPIO
- TWI_SDA
- UART_RX
- SPI_SS_A
- SPI_MISO
- (near J2) TWI_SCL
- (near J2) UART_TX
- (near J2) SPI_MOSI
- (near J2) SPI_SCK
- Input filter on USB power input.
- EXT1 extension header
- USB ID can be used to check if a OTG cable is plugged in or enable host mode.
- Date:
- PAGE:
- of
- TITLE:
- Document number:
- Revision:

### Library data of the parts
C21 C30 C31 C55 = A01-0321: Ceramic capacitor, SMD 0402, C0G, 50V, +/-5%; PartGroup: Capacitors,Ceramic,SMD 0402; Manufacturer: Murata; MPN: GRM1555C1H102JA01D; Tolerance: 5%
C29 C32 = A01-0046: Ceramic capacitor, SMD 0402, X7R, 25V, +/-10%; PartGroup: Capacitors,Ceramic,SMD 0402; TemperatureRange: -55 - +125 deg C
CONN1 = A08-2466: PHOENIX CONTACT  GMKDS 3/ 2-7,62  TERMINAL BLOCK, WIRE TO BRD, 2POS, 12AWG; PartGroup: Mechanical devices,Connectors,PCB screw connector; Manufacturer: Phoenix Contacts
CONN2 = A08-2465: TERMINAL BLOCK, WIRE TO BRD, 3POS, 12AWG; PartGroup: Mechanical devices,Connectors,PCB screw connector; Manufacturer: Phoenix Contacts
D10 D12 = A06-0236: Double rail-to-rail USB ESD protection diode; OrcadPartType: Integrated Circuits&Special function&Protection; Manufacturer: Philips; TemperatureRange: -40 to +85 C
J1 = A08-0191: 1x6 pin header, 2.54mm pitch, THM Pin-In-Paste; PartGroup: Mechanical devices,Connectors,Pin headers; Manufacturer: Freber; MPN: CD0750141X6T&R
J2 = A08-1513: Pin header, 2x10, Right Angle, 2.54mm, THM, Pin In Paste; PartGroup: Mechanical devices,Connectors,Pin headers
J4 J5 = A08-2112: Micro USB AB Connector, Standard SMT + DIP; PartGroup: Mechanical devices,Connectors,USB
L1 L6 = A03-0035: SMD RF inductor 0603. Z=470Ohm (@100MHz), Max R(dc)=0.65Ohm, Max current=1A; PartGroup: Inductors,EMI; Manufacturer: Murata; Tolerance: ±25%; TemperatureRange: -55°C to +125°C
R37 R42 = A02-0284: Thick film resistor, SMD 0402, 1/16W, 1%; PartGroup: Resistors,SMD,0402 1%; Manufacturer: KOA; MPN: RK73H1ETTP1004F; TemperatureRange: -55 - +125 deg C
R43 = A02-0200: Thick film resistor, SMD 0402, 1/16W, 1%; PartGroup: Resistors,SMD,0402 1%; TemperatureRange: -55 - +125 deg C

## Sheet ATBLDC24V_Bemf_Sensor.SchDoc: ATBLDC24V_schematic
size A3; Organization: ATMEL Chennai; Address1: 12th Floor; Address2: Prince Infocity II; Address3: 283 & 284, OMR; Address4: Chennai; Revision: 2; SheetNumber: 6; SheetTotal: 9; CheckedBy: MSK; DrawnBy: SAN/OJS; Engineer: SAN/OJS; PageSetup: Record=PageOptions¦CenterHorizontal=True¦CenterVertical=True¦PrintScale=1.01¦XCorrection=1.00¦YCorrection=1.00¦PrintKind=1¦BorderSize=5000000¦LeftOffset=0¦BottomOffset=0¦Orientation=2¦PaperLength=1000¦PaperWidth=1000¦Scale=100¦PaperSource=7¦PrintQuality=-4¦MediaType=1¦DitherType=10¦PaperKind=A3 (297 x 420 mm)¦PrintScaleMode=1
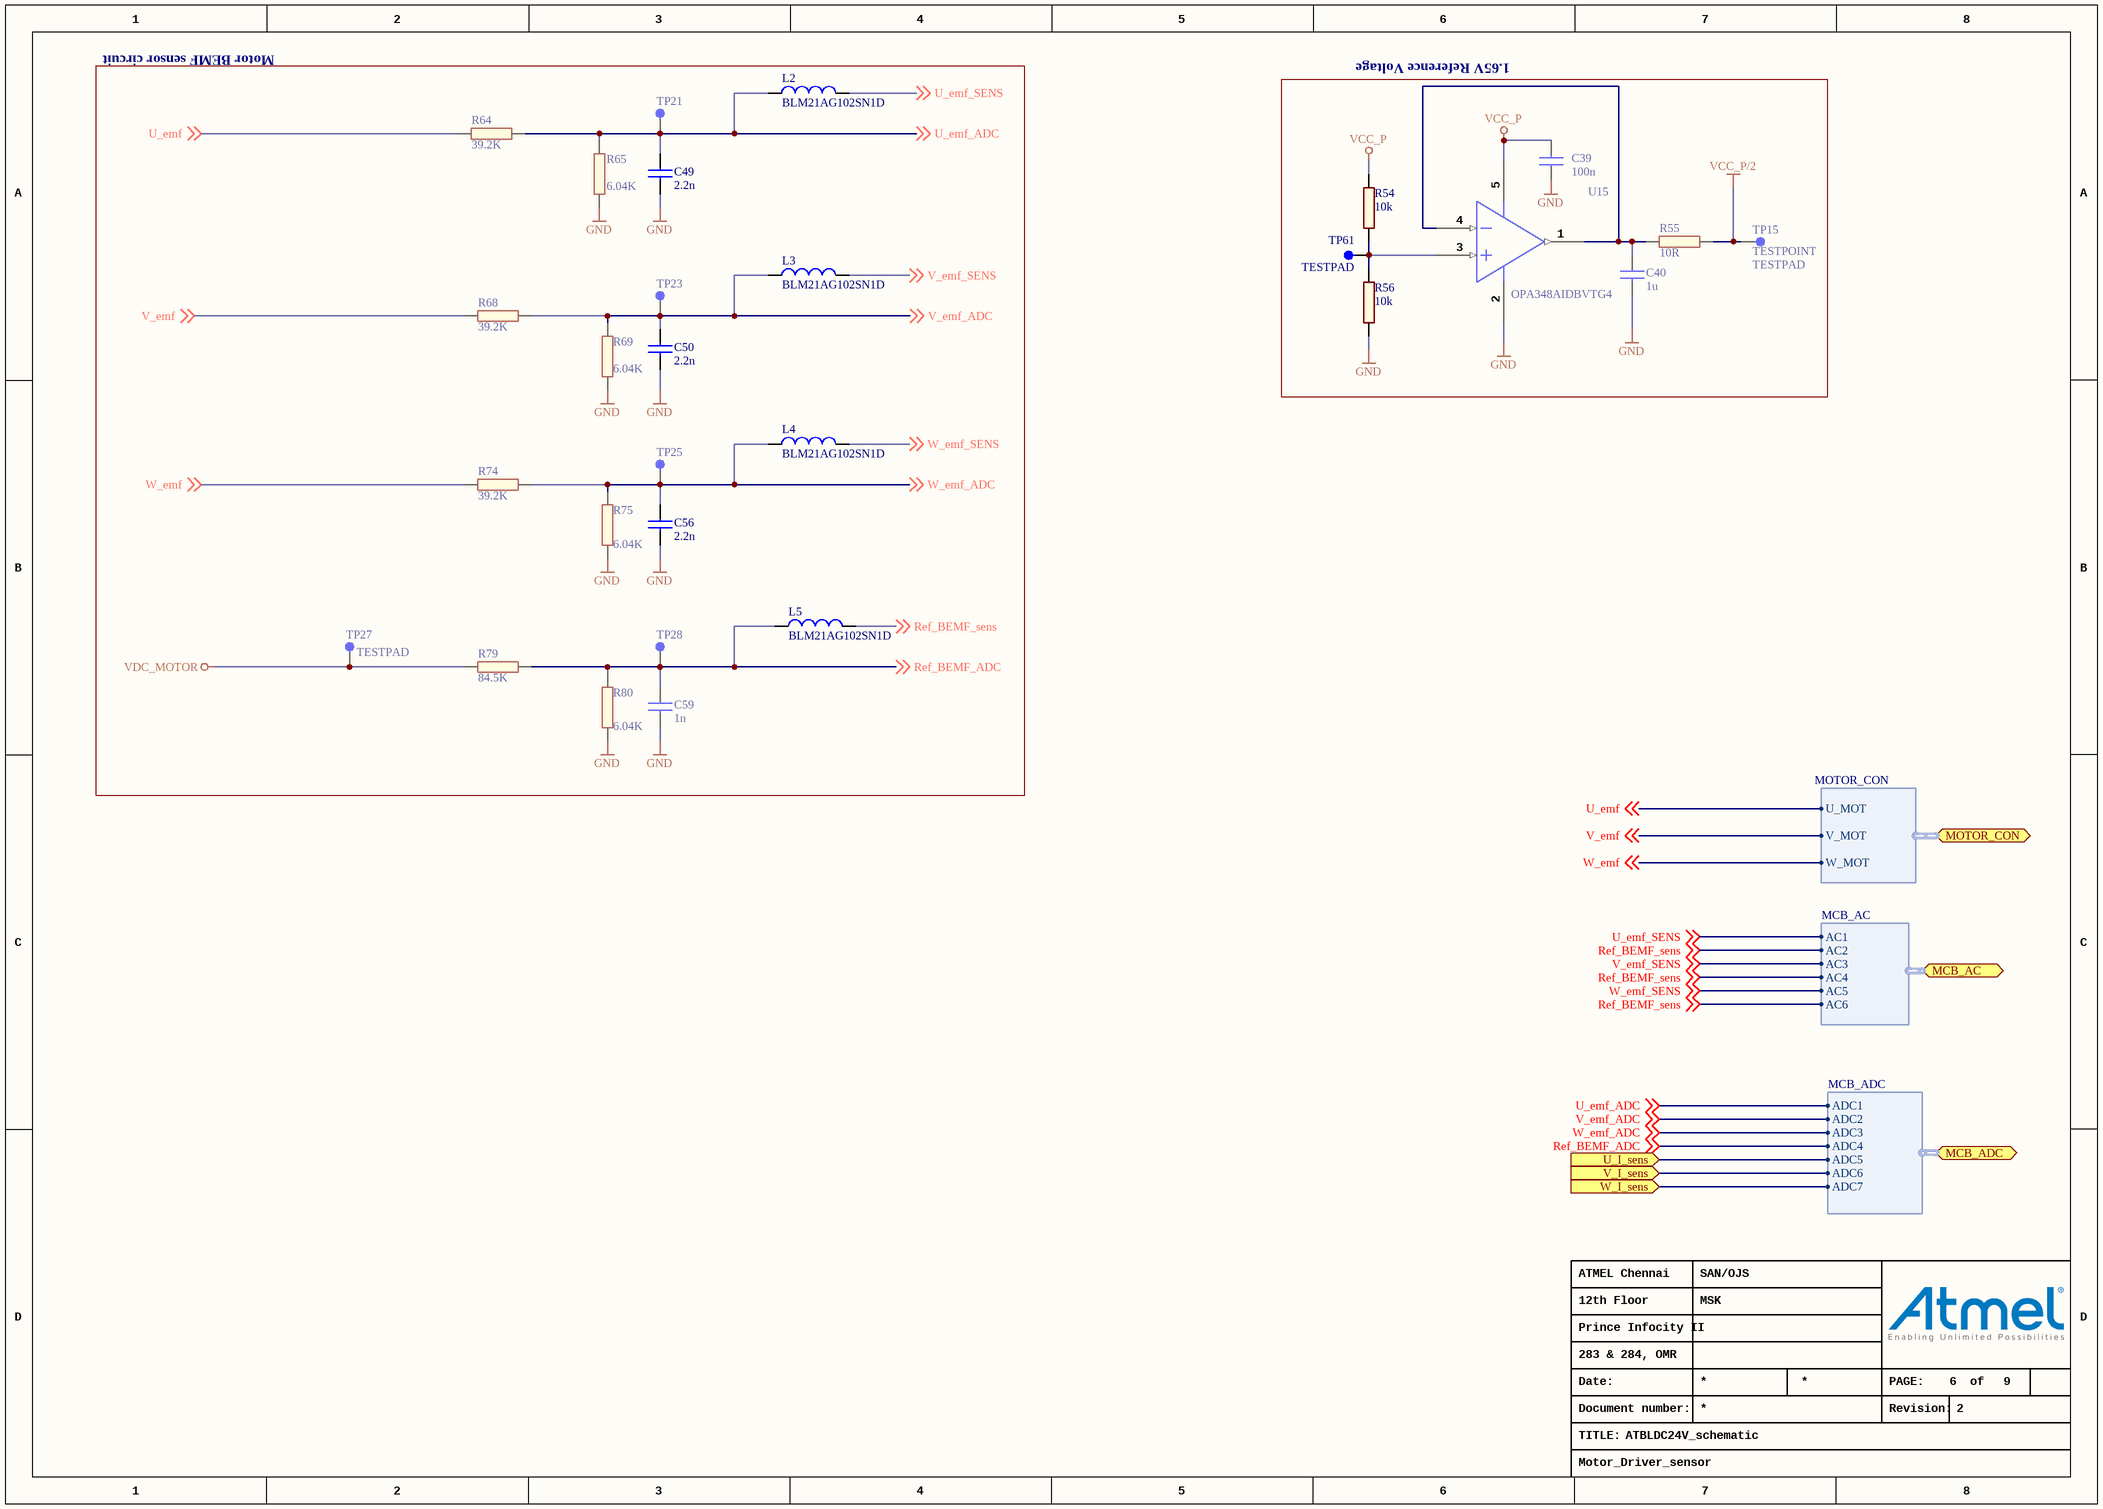
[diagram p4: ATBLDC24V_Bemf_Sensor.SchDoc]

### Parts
C39  value 100n  [AP1-00002]  (hidden comment: CAP-NONPOL)
C40  value 1u  [AP1-00026]  (hidden comment: CAP-NONPOL)
C49  value 2.2n  [AP1-00002]  (hidden comment: MPN back-ported from Escatec 29-09-2009)
C50  value 2.2n  [AP1-00002]  (hidden comment: MPN back-ported from Escatec 29-09-2009)
C56  value 2.2n  [AP1-00002]  (hidden comment: MPN back-ported from Escatec 29-09-2009)
C59  value 1n  [AP1-00002]  (hidden comment: MPN back-ported from Escatec 29-09-2009)
L2  value BLM21AG102SN1D  [AP3-00002]  (hidden comment: INDUCTOR)
L3  value BLM21AG102SN1D  [AP3-00002]  (hidden comment: INDUCTOR)
L4  value BLM21AG102SN1D  [AP3-00002]  (hidden comment: INDUCTOR)
L5  value BLM21AG102SN1D  [AP3-00002]  (hidden comment: INDUCTOR)
R54  value 10k  [AP2-00001]  (hidden comment: Farnell no.: 1717597)
R55  value 10R  [AP2-00001]  (hidden comment: R2)
R56  value 10k  [AP2-00001]  (hidden comment: Farnell no.: 1717597)
R64  value 39.2K  [AP2-00001]  (hidden comment: R2)
R65  value 6.04K  [AP2-00001]  (hidden comment: R2)
R68  value 39.2K  [AP2-00001]  (hidden comment: R2)
R69  value 6.04K  [AP2-00001]  (hidden comment: R2)
R74  value 39.2K  [AP2-00001]  (hidden comment: R2)
R75  value 6.04K  [AP2-00001]  (hidden comment: R2)
R79  value 84.5K  [AP2-00001]  (hidden comment: R2)
R80  value 6.04K  [AP2-00001]  (hidden comment: R2)
TP15  TESTPOINT  value TESTPAD  [AP8-00010]  (no BOM)
TP21  Through hole with 10mil annular ring  [AP8-00722]  (value not drawn)  (no BOM)
TP23  Through hole with 10mil annular ring  [AP8-00722]  (value not drawn)  (no BOM)
TP25  Through hole with 10mil annular ring  [AP8-00722]  (value not drawn)  (no BOM)
TP27  value TESTPAD  [AP8-00010]  (hidden comment: TESTPOINT)  (no BOM)
TP28  Through hole with 10mil annular ring  [AP8-00722]  (value not drawn)  (no BOM)
TP61  value TESTPAD  [AP8-00010]  (hidden comment: TESTPOINT)  (no BOM)
U15  value OPA348AIDBVTG4  [AP6-00087]

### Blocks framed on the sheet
Motor BEMF sensor circuit: C49 C50 C56 C59 L2-L5 R64 R65 R68 R69 R74 R75 R79 R80 TP21 TP23 TP25 TP27 TP28

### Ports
MCB_AC (harness MCB_AC), MCB_ADC (harness MCB_ADC), MOTOR_CON (harness MOTOR_CON), U_I_sens (in), V_I_sens (in), W_I_sens (in)

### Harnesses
MCB_ADC: ADC1, ADC2, ADC3, ADC4, ADC5, ADC6, ADC7
MCB_AC: AC1, AC2, AC3, AC4, AC5, AC6
MOTOR_CON: U_MOT, V_MOT, W_MOT

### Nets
GND: C39.1 C40.2 C49.2 C50.2 C56.2 C59.2 R56.1 R65.1 R69.1 R75.1 R80.1 U15.2(GND)
VCC_P: C39.2 R54.2 U15.5(VCC)
VCC_P/2: R55.2 TP15.1
VDC_MOTOR: R79.1 TP27.1
Ref_BEMF_ADC: C59.1 L5.1 R79.2 R80.2 TP28.1 ; off-sheet Ref_BEMF_ADC, port MCB_ADC.ADC4  [project net MOTOR_VDC]
Ref_BEMF_sens: L5.2 ; off-sheet Ref_BEMF_sens, port MCB_AC.AC2, port MCB_AC.AC4, port MCB_AC.AC6
U_emf: R64.1 ; off-sheet U_emf, port MOTOR_CON.U_MOT
U_emf_ADC: C49.1 L2.1 R64.2 R65.2 TP21.1 ; off-sheet U_emf_ADC, port MCB_ADC.ADC1  [project net BEMF_UADC]
U_emf_SENS: L2.2 ; off-sheet U_emf_SENS, port MCB_AC.AC1  [project net BEMF_UP]
USHUNT_ADC: port U_I_sens, port MCB_ADC.ADC5
V_emf: R68.1 ; off-sheet V_emf, port MOTOR_CON.V_MOT
V_emf_ADC: C50.1 L3.1 R68.2 R69.2 TP23.1 ; off-sheet V_emf_ADC, port MCB_ADC.ADC2  [project net BEMF_VADC]
V_emf_SENS: L3.2 ; off-sheet V_emf_SENS, port MCB_AC.AC3  [project net BEMF_VP]
VSHUNT_ADC: port V_I_sens, port MCB_ADC.ADC6
W_emf: R74.1 ; off-sheet W_emf, port MOTOR_CON.W_MOT
W_emf_ADC: C56.1 L4.1 R74.2 R75.2 TP25.1 ; off-sheet W_emf_ADC, port MCB_ADC.ADC3  [project net BEMF_WADC]
W_emf_SENS: L4.2 ; off-sheet W_emf_SENS, port MCB_AC.AC5  [project net BEMF_WP]
WSHUNT_ADC: port W_I_sens, port MCB_ADC.ADC7
NetC40_1: C40.1 R55.1 U15.1(OUT) U15.4(IN-)
NetR54_1: R54.1 R56.2 TP61.1 U15.3(IN+)

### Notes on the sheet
- 1.65V Reference Voltage

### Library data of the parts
C39 = A01-0087: Ceramic capacitor, SMD 0603, X7R, 16V, +/-10 %; PartGroup: Capacitors,Ceramic,SMD 0603; Manufacturer: AVX; MPN: 0603YC104KAT2A; TemperatureRange: -55 - +125 deg C
C40 = A01-0381: Capacitor, Ceramic, 1uF, 100V, 1206, X7R; PartGroup: Capacitors,Ceramic,SMD 1206; Manufacturer: tdk; MPN: C3216X7R2A105K; Tolerance: 10%
C49 C50 C56 = A01-0105: Ceramic capacitor, SMD 0603, X7R, 50V, ±10 %; PartGroup: Capacitors,Ceramic,SMD 0603; Manufacturer: Kemet; MPN: C0603C222K5RAC; TemperatureRange: -55 - +125 deg C; ComponentStatus: 'Active (verified)'
C59 = A01-0101: Ceramic capacitor, SMD 0603, X7R, 50V, ±10 %; PartGroup: Capacitors,Ceramic,SMD 0603; Manufacturer: AVX; MPN: 06035C102KAT2A; TemperatureRange: -55 - +125 deg C
L2-L5 = A03-0004: SMD RF inductor 0805. Z=1000Ohm (@100MHz), Max R(dc)=0.45Ohm, Max current=200mA; PartGroup: Inductors,EMI; Manufacturer: Murata; TemperatureRange: -55 - +125 deg. C
R54 R56 = A02-0959: as R44 on sheet ATBLDC24V_Driver
R55 = A02-0026: Thick film resistor, SMD 0603, 1/10W, 1%; PartGroup: Resistors,SMD,0603 1%; Manufacturer: KOA; MPN: RK73H1JTTD10R0F
R64 R68 R74 = A02-1013: Thick film resistor, SMD 0603, 1/10W, 1%; PartGroup: Resistors,SMD,0603 1%; Manufacturer: Panasonic; MPN: ERJ3EKF3922V
R65 R69 R75 R80 = A02-0997: Thick film resistor, SMD 0603, 1/10W, 1%; PartGroup: Resistors,SMD,0603 1%; Manufacturer: vishay; MPN: CRCW06036K04FKEA
R79 = A02-1014: Thick film resistor, SMD 0603, 1/10W, 1%; PartGroup: Resistors,SMD,0603 1%; Manufacturer: Panasonic; MPN: ERJ3EKF8452V
TP15 TP27 TP61 = A08-0004: as TP10 on sheet ATBLDC24V_Main_supply
TP21 TP23 TP25 TP28 = A08-1748: as TP13 on sheet ATBLDC24V_Driver
U15 = A06-1285: OP AMP, CMOS 1MHZ RRI/O, SOT-23-5; PartGroup: Integrated Circuits,General linear,OP-AMP; TemperatureRange: 0Â°C to +85Â°C

## Sheet ATBLDC24V_MCU.SchDoc: ATBLDC24V_schematic
size A3; Organization: ATMEL Chennai; Address1: 12th Floor; Address2: Prince Infocity II; Address3: 283 & 284, OMR,; Address4: Chennai; Revision: 2; SheetNumber: 4; SheetTotal: 9; CheckedBy: MSK; DrawnBy: SAN/OJS; Engineer: SAN/OJS; PageSetup: Record=PageOptions¦CenterHorizontal=True¦CenterVertical=True¦PrintScale=1.01¦XCorrection=1.00¦YCorrection=1.00¦PrintKind=1¦BorderSize=5000000¦LeftOffset=0¦BottomOffset=0¦Orientation=2¦PaperLength=1000¦PaperWidth=1000¦Scale=100¦PaperSource=7¦PrintQuality=-4¦MediaType=1¦DitherType=10¦PaperKind=A3 (297 x 420 mm)¦PrintScaleMode=1
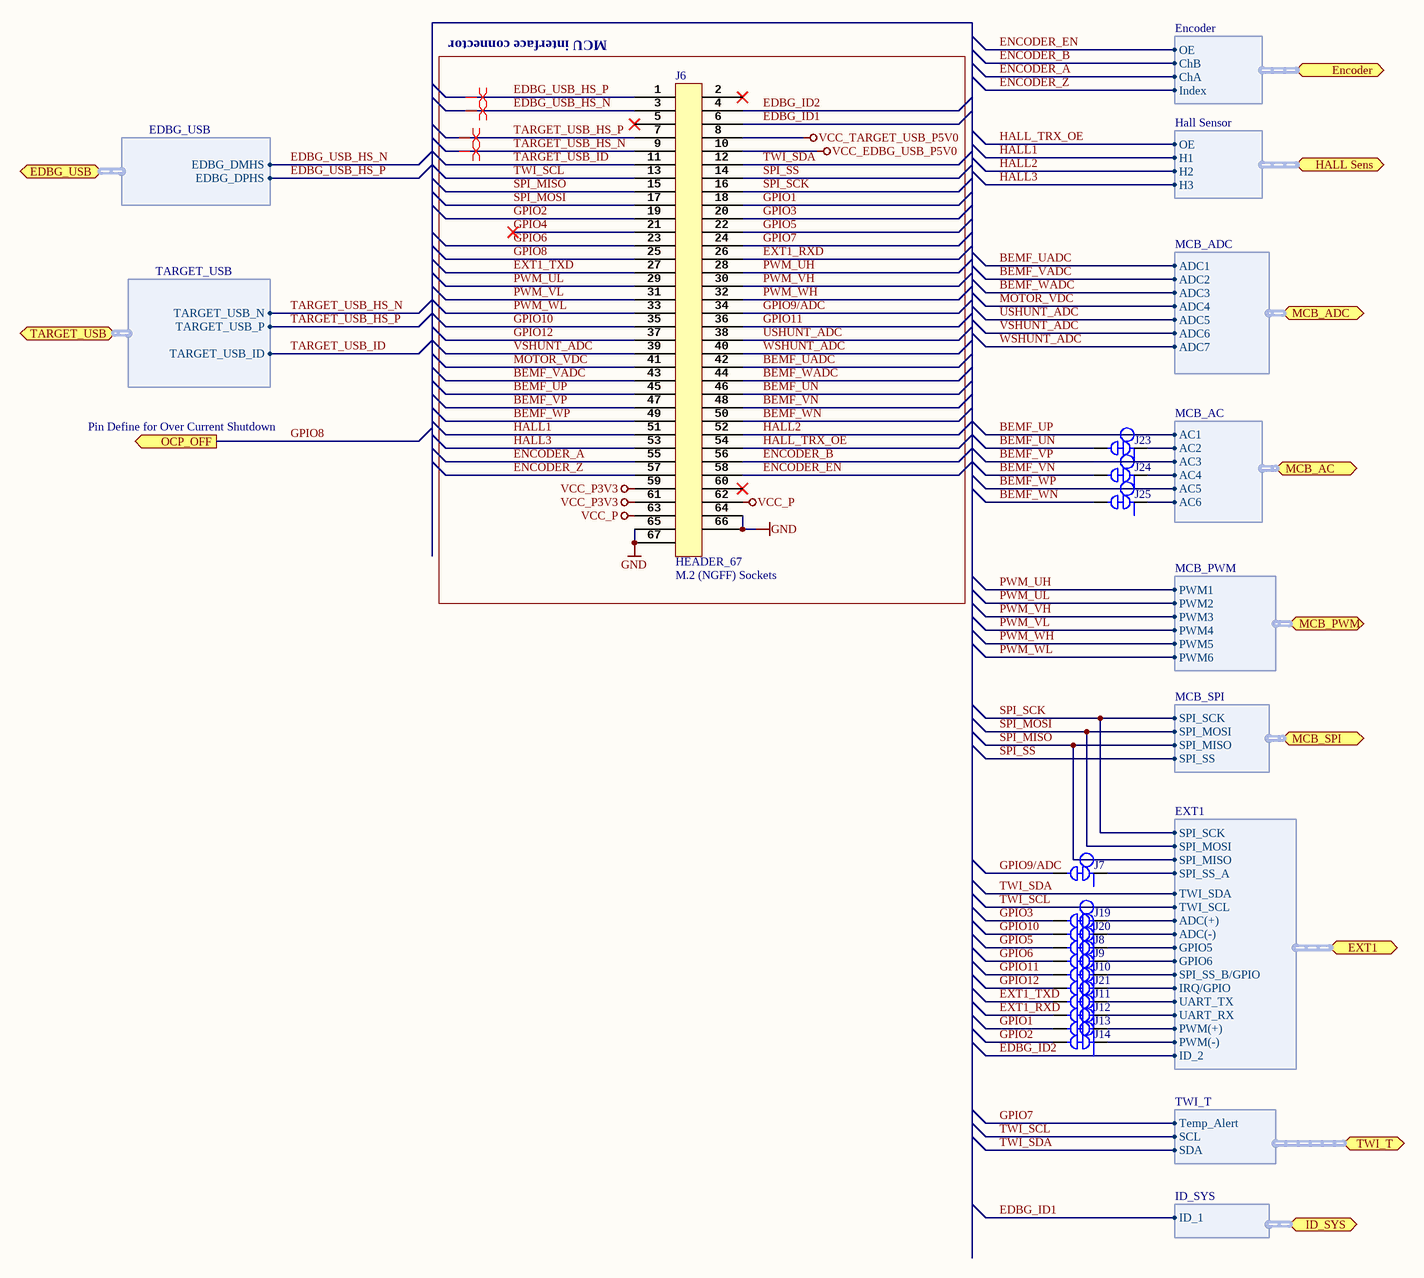
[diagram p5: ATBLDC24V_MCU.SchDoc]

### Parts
J6  HEADER_67  value M.2 (NGFF) Sockets  [AP8-00916]
J7  PCB trace only  [AP9-00035]  (value not drawn)  (net tie, no BOM)
J8  PCB trace only  [AP9-00035]  (value not drawn)  (net tie, no BOM)
J9  PCB trace only  [AP9-00035]  (value not drawn)  (net tie, no BOM)
J10  PCB trace only  [AP9-00035]  (value not drawn)  (net tie, no BOM)
J11  PCB trace only  [AP9-00035]  (value not drawn)  (net tie, no BOM)
J12  PCB trace only  [AP9-00035]  (value not drawn)  (net tie, no BOM)
J13  PCB trace only  [AP9-00035]  (value not drawn)  (net tie, no BOM)
J14  PCB trace only  [AP9-00035]  (value not drawn)  (net tie, no BOM)
J19  PCB trace only  [AP9-00035]  (value not drawn)  (net tie, no BOM)
J20  PCB trace only  [AP9-00035]  (value not drawn)  (net tie, no BOM)
J21  PCB trace only  [AP9-00035]  (value not drawn)  (net tie, no BOM)
J23  PCB trace only  [AP9-00035]  (value not drawn)  (net tie, no BOM)
J24  PCB trace only  [AP9-00035]  (value not drawn)  (net tie, no BOM)
J25  PCB trace only  [AP9-00035]  (value not drawn)  (net tie, no BOM)

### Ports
EDBG_USB (harness EDBG_USB), Encoder (harness Encoder), EXT1 (harness EXT1), HALL Sens (harness Hall Sensor), ID_SYS (harness ID_SYS), MCB_AC (harness MCB_AC), MCB_ADC (harness MCB_ADC), MCB_PWM (harness MCB_PWM), MCB_SPI (harness MCB_SPI), OCP_OFF (out), TARGET_USB (harness TARGET_USB), TWI_T (harness TWI_T)

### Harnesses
MCB_PWM: PWM1, PWM2, PWM3, PWM4, PWM5, PWM6
MCB_SPI: SPI_SCK, SPI_MOSI, SPI_MISO, SPI_SS
ID_SYS: ID_1
MCB_ADC: ADC1, ADC2, ADC3, ADC4, ADC5, ADC6, ADC7
EXT1: ADC(+), ADC(-), GPIO5, GPIO6, PWM(+), PWM(-), IRQ/GPIO, SPI_SS_B/GPIO, TWI_SDA, TWI_SCL, UART_RX, UART_TX, SPI_SS_A, SPI_MOSI, SPI_MISO, SPI_SCK, ID_2
TWI_T: SDA, SCL, Temp_Alert
EDBG_USB: EDBG_DMHS, EDBG_DPHS
TARGET_USB: TARGET_USB_N, TARGET_USB_P, TARGET_USB_ID
Hall Sensor: H1, H2, H3, OE
MCB_AC: AC1, AC2, AC3, AC4, AC5, AC6
Encoder: ChB, ChA, Index, OE

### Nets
GND: J6.64 J6.65 J6.66 J6.67
VCC_EDBG_USB_P5V0: J6.10
VCC_P: J6.62 J6.63
VCC_P3V3: J6.59 J6.61
VCC_TARGET_USB_P5V0: J6.8
BEMF_UADC: J6.42 ; port MCB_ADC.ADC1
BEMF_UN: J6.46 J23.2
BEMF_UP: J6.45 ; port MCB_AC.AC1
BEMF_VADC: J6.43 ; port MCB_ADC.ADC2
BEMF_VN: J6.48 J24.2
BEMF_VP: J6.47 ; port MCB_AC.AC3
BEMF_WADC: J6.44 ; port MCB_ADC.ADC3
BEMF_WN: J6.50 J25.2
BEMF_WP: J6.49 ; port MCB_AC.AC5
EDBG_ID1: J6.6 ; port ID_SYS.ID_1
EDBG_ID2: J6.4 ; port EXT1.ID_2
EDBG_USB_HS_N: J6.3 ; port EDBG_USB.EDBG_DMHS
EDBG_USB_HS_P: J6.1 ; port EDBG_USB.EDBG_DPHS
ENCODER_A: J6.55 ; port Encoder.ChA
ENCODER_B: J6.56 ; port Encoder.ChB
ENCODER_EN: J6.58 ; port Encoder.OE
ENCODER_Z: J6.57 ; port Encoder.Index
EXT1_RXD: J6.26 J12.2
EXT1_TXD: J6.27 J11.2
GPIO1: J6.18 J13.2
GPIO2: J6.19 J14.2
GPIO3: J6.20 J19.2
GPIO4: J6.21
GPIO5: J6.22 J8.2
GPIO6: J6.23 J9.2
GPIO7: J6.24 ; port TWI_T.Temp_Alert
GPIO8: J6.25 ; port OCP_OFF
GPIO9/ADC: J6.34 J7.2
GPIO10: J6.35 J20.2
GPIO11: J6.36 J10.2
GPIO12: J6.37 J21.2
HALL1: J6.51 ; port HALL Sens.H1
HALL2: J6.52 ; port HALL Sens.H2
HALL3: J6.53 ; port HALL Sens.H3
HALL_TRX_OE: J6.54 ; port HALL Sens.OE
MOTOR_VDC: J6.41 ; port MCB_ADC.ADC4
PWM_UH: J6.28 ; port MCB_PWM.PWM1
PWM_UL: J6.29 ; port MCB_PWM.PWM2
PWM_VH: J6.30 ; port MCB_PWM.PWM3
PWM_VL: J6.31 ; port MCB_PWM.PWM4
PWM_WH: J6.32 ; port MCB_PWM.PWM5
PWM_WL: J6.33 ; port MCB_PWM.PWM6
Ref_BEMF_sens: J23.1 J24.1 J25.1 ; port MCB_AC.AC2, port MCB_AC.AC4, port MCB_AC.AC6
SPI_MISO: J6.15 ; port MCB_SPI.SPI_MISO, port EXT1.SPI_MISO
SPI_MOSI: J6.17 ; port MCB_SPI.SPI_MOSI, port EXT1.SPI_MOSI
SPI_SCK: J6.16 ; port MCB_SPI.SPI_SCK, port EXT1.SPI_SCK
SPI_SS: J6.14 ; port MCB_SPI.SPI_SS
TARGET_USB_HS_N: J6.9 ; port TARGET_USB.TARGET_USB_N
TARGET_USB_HS_P: J6.7 ; port TARGET_USB.TARGET_USB_P
TARGET_USB_ID: J6.11 ; port TARGET_USB.TARGET_USB_ID  [project net PA03_USB_ID]
TWI_SCL: J6.13 ; port EXT1.TWI_SCL, port TWI_T.SCL
TWI_SDA: J6.12 ; port EXT1.TWI_SDA, port TWI_T.SDA
USHUNT_ADC: J6.38 ; port MCB_ADC.ADC5
VSHUNT_ADC: J6.39 ; port MCB_ADC.ADC6
WSHUNT_ADC: J6.40 ; port MCB_ADC.ADC7
NetJ2_3: J19.1 ; port EXT1.ADC(+)
NetJ2_4: J20.1 ; port EXT1.ADC(-)
NetJ2_5: J8.1 ; port EXT1.GPIO5
NetJ2_6: J9.1 ; port EXT1.GPIO6
NetJ2_7: J13.1 ; port EXT1.PWM(+)
NetJ2_8: J14.1 ; port EXT1.PWM(-)
NetJ2_9: J21.1 ; port EXT1.IRQ/GPIO
NetJ2_10: J10.1 ; port EXT1.SPI_SS_B/GPIO
NetJ2_13: J12.1 ; port EXT1.UART_RX
NetJ2_14: J11.1 ; port EXT1.UART_TX
NetJ2_15: J7.1 ; port EXT1.SPI_SS_A

Not connected (* = marked no-connect by the designer): J6 2* 5* 60*

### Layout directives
differential pair: EDBG_USB_HS_N, EDBG_USB_HS_P, TARGET_USB_HS_N, TARGET_USB_HS_P

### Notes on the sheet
- MCU interface connector
- Pin Define for Over Current Shutdown

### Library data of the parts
J6 = A08-2293: M.2 (NGFF) Sockets for Adapter PCB; PartGroup: Mechanical devices,Other; Manufacturer: TE Connectivity; MPN: 2199230-3
J7-J14 J19-J21 J23-J25 = A09-0473: Default closed SMD strap; PartGroup: Mechanical devices,PCB implemented components; Value: SMD-STRAP_CLOSED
